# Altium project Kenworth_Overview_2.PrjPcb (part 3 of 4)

## Sheet Special_Equipment_Cabinet_Overview.SchDoc: <Document>
size Letter; Engineer: <Engineer>; Organization: UPEL; Address1: USU Power Electronics Lab; Address2: USTAR Building 620, RM 118; Address3: 1600 N 620 E; Address4: North Logan, UT 84341; DocumentNumber: 2; Revision: v1; SheetNumber: 2; SheetTotal: 16
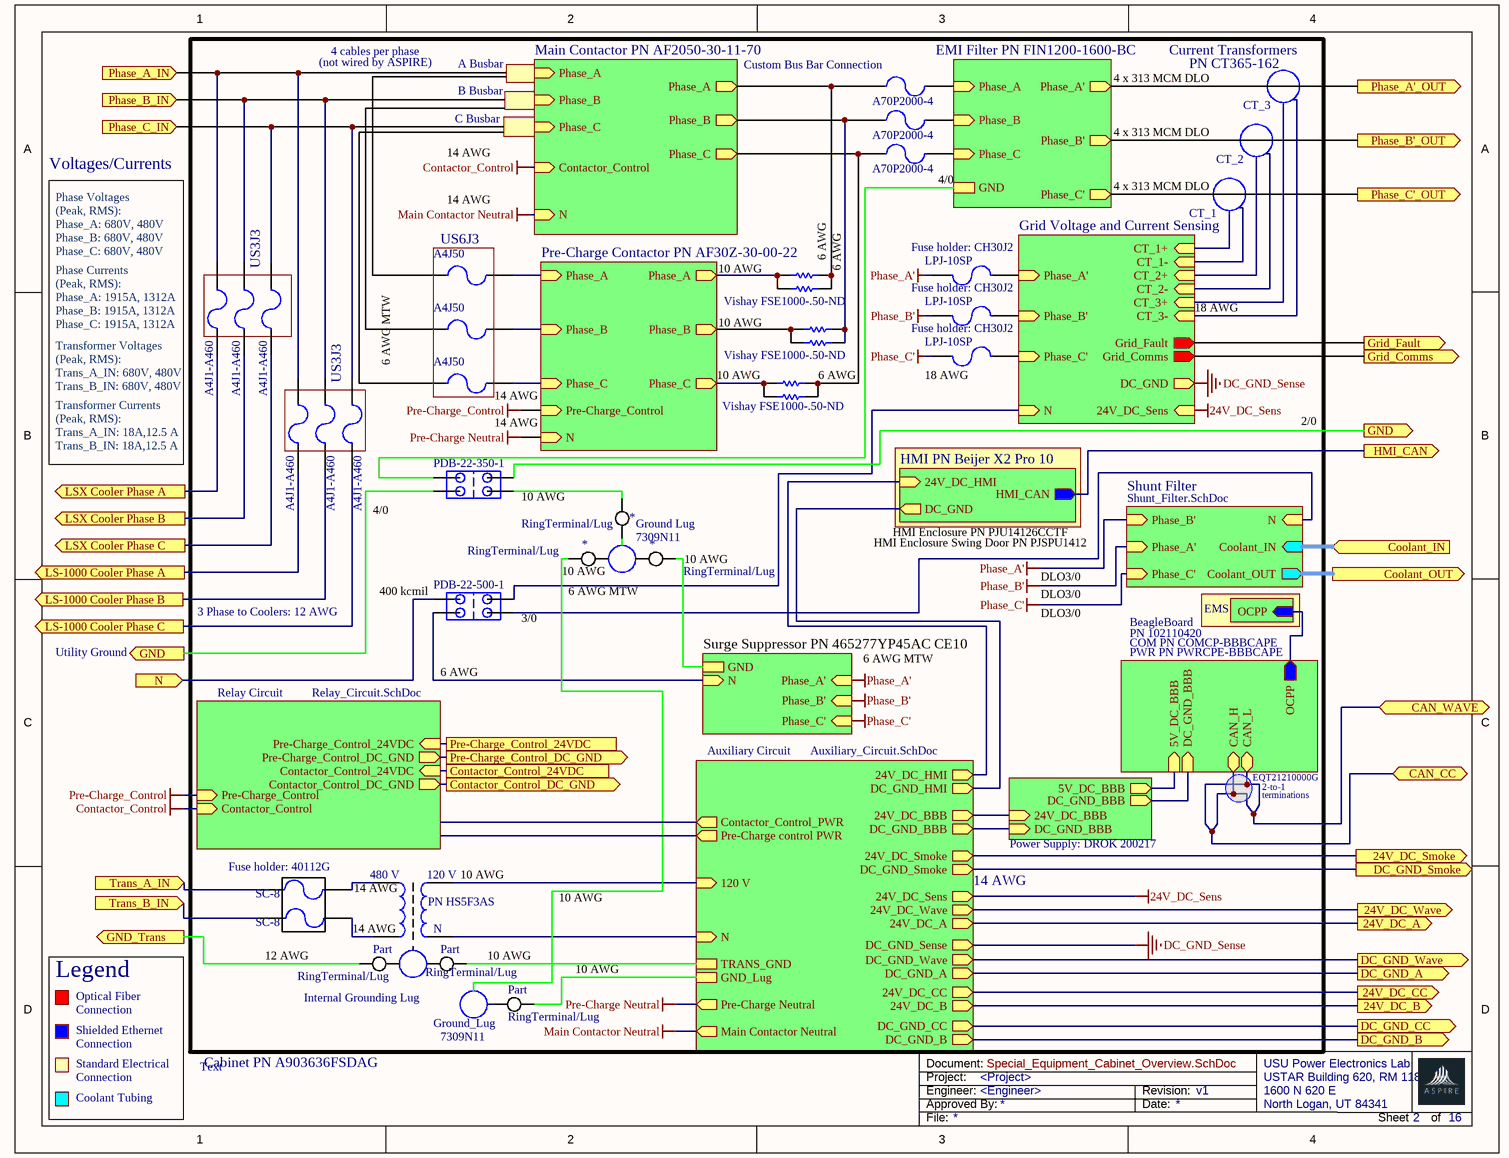
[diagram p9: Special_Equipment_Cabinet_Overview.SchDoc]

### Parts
(Parts that share a designator on the sheet are numbered #1, #2 ... from top to bottom, then left to right.)
7309N11#2  Ground_Lug_Three_Pin  (value not drawn)
7309N11#3  Ground_Lug_Three_Pin  (value not drawn)
7309N11#4  Ground_Lug
*#2  CT_3
*#3  CT_2
*#4  CT_1
*#5  RingTerminal/Lug
*#6  RingTerminal/Lug
*#7  RingTerminal/Lug
F64  A70P2000-4  [PIN-W2/E2.8]
F65  A70P2000-4  [PIN-W2/E2.8]
F66  A70P2000-4  [PIN-W2/E2.8]
F67  A4J50  [PIN-W2/E2.8]
F68  Fuse 2  [PIN-W2/E2.8]  (value not drawn)
F69  A4J50  [PIN-W2/E2.8]
F70  Fuse 2  [PIN-W2/E2.8]  (value not drawn)
F71  A4J50  [PIN-W2/E2.8]
F72  Fuse 2  [PIN-W2/E2.8]  (value not drawn)
F?#1  A4J1-A460  [PIN-W2/E2.8]
F?#2  A4J1-A460  [PIN-W2/E2.8]
F?#3  A4J1-A460  [PIN-W2/E2.8]
F?#4  A4J1-A460  [PIN-W2/E2.8]
F?#5  A4J1-A460  [PIN-W2/E2.8]
F?#6  A4J1-A460  [PIN-W2/E2.8]
J16  PDB-22-350-1
J17  PDB-22-500-1
Part#1  RingTerminal/Lug
Part#2  RingTerminal/Lug
Part#3  RingTerminal/Lug
SC-8#1  Fuse 2  [PIN-W2/E2.8]  (value not drawn)
SC-8#2  Fuse 2  [PIN-W2/E2.8]  (value not drawn)
T1  PN HS5F3AS  [TRANS]
Vishay_FSE1  Res1  [AXIAL-0.3]  (value not drawn)
Vishay_FSE2  Res1  [AXIAL-0.3]  (value not drawn)
Vishay_FSE3  Res1  [AXIAL-0.3]  (value not drawn)
Vishay_FSE1000-.50-ND#1  Res1  [AXIAL-0.3]  (value not drawn)
Vishay_FSE1000-.50-ND#2  Res1  [AXIAL-0.3]  (value not drawn)
Vishay_FSE1000-.50-ND#3  Res1  [AXIAL-0.3]  (value not drawn)

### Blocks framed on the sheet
US6J3: F67 F69 F71
US3J3: F?#1-F?#3
US3J3: F?#4-F?#6

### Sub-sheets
Auxiliary Circuit = Auxiliary_Circuit.SchDoc: 24V_DC_A (out), DC_GND_B (out), DC_GND_CC (out), 24V_DC_Wave (out), DC_GND_Wave (out), DC_GND_A (out), 24V_DC_CC (out), 24V_DC_B (out), 24V_DC_Sens (out), DC_GND_Sense (out), Pre-Charge Neutral (out), Main Contactor Neutral (out), 120 V (in), N (in), Contactor_Control_PWR (out), Pre-Charge control PWR (out), DC_GND_Smoke (out), 24V_DC_Smoke (out), TRANS_GND, GND_Lug, 24V_DC_HMI (out), DC_GND_HMI (out), 24V_DC_BBB (out), DC_GND_BBB (out)
BeagleBoard = File Name (file not in this document): OCPP (out), CAN_H (bidir), CAN_L (bidir), 5V_DC_BBB (in), DC_GND_BBB (in)
EMI Filter PN FIN1200-1600-BC = File Name (file not in this document): Phase_A (in), Phase_B (in), Phase_C (in), Phase_C' (out), Phase_B' (out), Phase_A' (out), GND
EMS = File Name (file not in this document): OCPP (in)
Grid Voltage and Current Sensing = File Name (file not in this document): Phase_A' (in), Phase_B' (in), Phase_C' (in), N (in), Grid_Comms (out), Grid_Fault (out), 24V_DC_Sens (in), CT_1+ (in), CT_3+ (in), CT_2+ (in), DC_GND (out), CT_1- (in), CT_2- (in), CT_3- (in)
HMI PN Beijer X2 Pro 10 = File Name (file not in this document): 24V_DC_HMI (in), HMI_CAN (out), DC_GND (out)
Main Contactor PN AF2050-30-11-70 = File Name (file not in this document): Phase_A (in), Phase_B (in), Phase_C (in), N (in), Contactor_Control (in), Phase_A (out), Phase_B (out), Phase_C (out)
Power Supply: DROK 200217 = File Name (file not in this document): 5V_DC_BBB (out), DC_GND_BBB (out), 24V_DC_BBB (in), DC_GND_BBB (in)
Pre-Charge Contactor PN AF30Z-30-00-22 = File Name (file not in this document): Phase_B (in), Phase_C (in), Phase_A (out), Phase_B (out), Phase_C (out), Phase_A (in), Pre-Charge_Control (in), N (in)
Relay Circuit = Relay_Circuit.SchDoc: Contactor_Control_24VDC (in), Pre-Charge_Control_DC_GND (out), Pre-Charge_Control (in), Pre-Charge_Control_24VDC (in), Contactor_Control (in), Contactor_Control_DC_GND (out)
Shunt Filter = Shunt_Filter.SchDoc: Phase_B' (in), Phase_A' (in), Phase_C' (in), N (in), Coolant_IN (in), Coolant_OUT (out)
Surge Suppressor PN 465277YP45AC CE10 = File Name (file not in this document): Phase_A' (in), Phase_B' (in), Phase_C' (in), N (in), GND

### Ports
24V_DC_A (out), 24V_DC_B (out), 24V_DC_CC (out), 24V_DC_Smoke (out), 24V_DC_Wave (out), CAN_CC (bidir), CAN_WAVE (bidir), Contactor_Control_24VDC, Contactor_Control_DC_GND (out), Coolant_IN (in), Coolant_OUT (out), DC_GND_A (out), DC_GND_B (out), DC_GND_CC (out), DC_GND_Smoke (out), DC_GND_Wave (out), GND (out), GND_Trans (out), Grid_Comms (out), Grid_Fault (out), HMI_CAN (out), LS-1000 Cooler Phase A (out), LS-1000 Cooler Phase B (out), LS-1000 Cooler Phase C (out), LSX Cooler Phase A (out), LSX Cooler Phase B (out), LSX Cooler Phase C (out), N (in), Phase_A'_OUT (out), Phase_A_IN (in), Phase_B'_OUT (out), Phase_B_IN (in), Phase_C'_OUT (out), Phase_C_IN (in), Pre-Charge_Control_24VDC, Pre-Charge_Control_DC_GND (out), Trans_A_IN (in), Trans_B_IN (in)

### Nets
24V_DC_Sens: sheet Grid Voltage and Current Sensing/24V_DC_Sens, sheet Auxiliary Circuit/24V_DC_Sens
Contactor_Control: sheet Main Contactor PN AF2050-30-11-70/Contactor_Control, sheet Relay Circuit/Contactor_Control
DC_GND_Sense: sheet Grid Voltage and Current Sensing/DC_GND, sheet Auxiliary Circuit/DC_GND_Sense
Main Contactor Neutral: sheet Main Contactor PN AF2050-30-11-70/N, sheet Auxiliary Circuit/Main Contactor Neutral
Phase_A': F68.2 ; sheet Surge Suppressor PN 465277YP45AC CE10/Phase_A', sheet Shunt Filter/Phase_B'
Phase_B': F70.2 ; sheet Surge Suppressor PN 465277YP45AC CE10/Phase_B', sheet Shunt Filter/Phase_A'
Phase_C': F72.2 ; sheet Surge Suppressor PN 465277YP45AC CE10/Phase_C', sheet Shunt Filter/Phase_C'
Pre-Charge Neutral: sheet Pre-Charge Contactor PN AF30Z-30-00-22/N, sheet Auxiliary Circuit/Pre-Charge Neutral
Pre-Charge_Control: sheet Pre-Charge Contactor PN AF30Z-30-00-22/Pre-Charge_Control, sheet Relay Circuit/Pre-Charge_Control
24V_DC_A: port 24V_DC_A, sheet Auxiliary Circuit/24V_DC_A
24V_DC_B: port 24V_DC_B, sheet Auxiliary Circuit/24V_DC_B
24V_DC_CC: port 24V_DC_CC, sheet Auxiliary Circuit/24V_DC_CC
24V_DC_HMI: sheet HMI PN Beijer X2 Pro 10/24V_DC_HMI, sheet Auxiliary Circuit/24V_DC_HMI
24V_DC_Smoke: port 24V_DC_Smoke, sheet Auxiliary Circuit/24V_DC_Smoke
24V_DC_Wave: port 24V_DC_Wave, sheet Auxiliary Circuit/24V_DC_Wave
120 V: T1.3 ; sheet Auxiliary Circuit/120 V
CAN_CC: port CAN_WAVE, port CAN_CC, sheet BeagleBoard/CAN_H, sheet BeagleBoard/CAN_L
Contactor_Control_24VDC: port Contactor_Control_24VDC, sheet Relay Circuit/Contactor_Control_24VDC
Contactor_Control_DC_GND: port Contactor_Control_DC_GND, sheet Relay Circuit/Contactor_Control_DC_GND
Coolant_IN: port Coolant_IN, sheet Shunt Filter/Coolant_IN
Coolant_OUT: port Coolant_OUT, sheet Shunt Filter/Coolant_OUT
DC_GND_A: port DC_GND_A, sheet Auxiliary Circuit/DC_GND_A
DC_GND_B: port DC_GND_B, sheet Auxiliary Circuit/DC_GND_B
DC_GND_CC: port DC_GND_CC, sheet Auxiliary Circuit/DC_GND_CC
DC_GND_HMI: sheet HMI PN Beijer X2 Pro 10/DC_GND, sheet Auxiliary Circuit/DC_GND_HMI
DC_GND_Smoke: port DC_GND_Smoke, sheet Auxiliary Circuit/DC_GND_Smoke
DC_GND_Wave: port DC_GND_Wave, sheet Auxiliary Circuit/DC_GND_Wave
GND: J16.2 J16.4 ; port GND
GND_Trans: Part#1.2_13 ; port GND_Trans
Grid_Comms: port Grid_Comms, sheet Grid Voltage and Current Sensing/Grid_Comms
Grid_Fault: port Grid_Fault, sheet Grid Voltage and Current Sensing/Grid_Fault
HMI_CAN: port HMI_CAN, sheet HMI PN Beijer X2 Pro 10/HMI_CAN
LS-1000 Cooler Phase A: F?#4.1 ; port LS-1000 Cooler Phase A
LS-1000 Cooler Phase B: F?#5.1 ; port LS-1000 Cooler Phase B
LS-1000 Cooler Phase C: F?#6.1 ; port LS-1000 Cooler Phase C
LSX Cooler Phase A: F?#1.1 ; port LSX Cooler Phase A
LSX Cooler Phase B: F?#2.1 ; port LSX Cooler Phase B
LSX Cooler Phase C: F?#3.1 ; port LSX Cooler Phase C
N: T1.4 ; sheet Auxiliary Circuit/N
N: J17.1 ; sheet Shunt Filter/N  [a separate net that carries the same name]
N: J17.4 ; port N  [a separate net that carries the same name]
Phase_A'_OUT: port Phase_A'_OUT, sheet EMI Filter PN FIN1200-1600-BC/Phase_A'
Phase_A_IN: F?#1.2 F?#4.2 ; port Phase_A_IN
Phase_B'_OUT: port Phase_B'_OUT, sheet EMI Filter PN FIN1200-1600-BC/Phase_B'
Phase_B_IN: F?#2.2 F?#5.2 ; port Phase_B_IN
Phase_C'_OUT: port Phase_C'_OUT, sheet EMI Filter PN FIN1200-1600-BC/Phase_C'
Phase_C_IN: F?#3.2 F?#6.2 ; port Phase_C_IN
Pre-Charge_Control_24VDC: port Pre-Charge_Control_24VDC, sheet Relay Circuit/Pre-Charge_Control_24VDC
Pre-Charge_Control_DC_GND: port Pre-Charge_Control_DC_GND, sheet Relay Circuit/Pre-Charge_Control_DC_GND
Trans_A_IN: SC-8#1.1 ; port Trans_A_IN
Trans_B_IN: SC-8#2.1 ; port Trans_B_IN
TRANS_GND: Part#2.2_12 ; sheet Auxiliary Circuit/TRANS_GND
Net7309N11#2_5: 7309N11#2.5 *#5.2_12
Net7309N11#2_5: 7309N11#2.5 *#7.2_13  [a separate net that carries the same name]
Net7309N11#2_5: 7309N11#2.5 *#6.2_12  [a separate net that carries the same name]
Net7309N11#3_5: 7309N11#3.5 Part#2.2_13
Net7309N11#3_5: 7309N11#3.5 Part#1.2_12  [a separate net that carries the same name]
Net7309N11#4_5: 7309N11#4.5 *#6.2_13
Net7309N11#4_5: 7309N11#4.5 Part#3.2_13  [a separate net that carries the same name]
Net*#2_4: *#2.4 ; sheet Grid Voltage and Current Sensing/CT_3+
Net*#2_4: *#2.4 ; sheet Grid Voltage and Current Sensing/CT_3-  [a separate net that carries the same name]
Net*#3_4: *#3.4 ; sheet Grid Voltage and Current Sensing/CT_2+
Net*#3_4: *#3.4 ; sheet Grid Voltage and Current Sensing/CT_2-  [a separate net that carries the same name]
Net*#4_4: *#4.4 ; sheet Grid Voltage and Current Sensing/CT_1+
Net*#4_4: *#4.4 ; sheet Grid Voltage and Current Sensing/CT_1-  [a separate net that carries the same name]
Net*#5_2_13: *#5.2_13 J16.1
Net*#7_2_12: *#7.2_12 ; sheet Surge Suppressor PN 465277YP45AC CE10/GND
NetF64_1: F64.1 Vishay_FSE1.2 Vishay_FSE1000-.50-ND#1.2 ; sheet Main Contactor PN AF2050-30-11-70/Phase_A
NetF64_2: F64.2 ; sheet EMI Filter PN FIN1200-1600-BC/Phase_A
NetF65_1: F65.1 Vishay_FSE2.2 Vishay_FSE1000-.50-ND#2.2 ; sheet Main Contactor PN AF2050-30-11-70/Phase_B
NetF65_2: F65.2 ; sheet EMI Filter PN FIN1200-1600-BC/Phase_B
NetF66_1: F66.1 Vishay_FSE3.2 Vishay_FSE1000-.50-ND#3.2 ; sheet Main Contactor PN AF2050-30-11-70/Phase_C
NetF66_2: F66.2 ; sheet EMI Filter PN FIN1200-1600-BC/Phase_C
NetF67_2: F67.2 ; sheet Pre-Charge Contactor PN AF30Z-30-00-22/Phase_A
NetF68_1: F68.1 ; sheet Grid Voltage and Current Sensing/Phase_A'
NetF69_2: F69.2 ; sheet Pre-Charge Contactor PN AF30Z-30-00-22/Phase_B
NetF70_1: F70.1 ; sheet Grid Voltage and Current Sensing/Phase_B'
NetF71_2: F71.2 ; sheet Pre-Charge Contactor PN AF30Z-30-00-22/Phase_C
NetF72_1: F72.1 ; sheet Grid Voltage and Current Sensing/Phase_C'
NetJ16_4: J16.4 ; sheet EMI Filter PN FIN1200-1600-BC/GND
NetJ17_2: J17.2 ; sheet Grid Voltage and Current Sensing/N
NetJ17_4: J17.4 ; sheet Surge Suppressor PN 465277YP45AC CE10/N
NetPart#3_2_12: Part#3.2_12 ; sheet Auxiliary Circuit/GND_Lug
NetSC-8#1_2: SC-8#1.2 T1.1
NetSC-8#2_2: SC-8#2.2 T1.2
NetVishay_FSE1_1: Vishay_FSE1.1 Vishay_FSE1000-.50-ND#1.1 ; sheet Pre-Charge Contactor PN AF30Z-30-00-22/Phase_A
NetVishay_FSE2_1: Vishay_FSE2.1 Vishay_FSE1000-.50-ND#2.1 ; sheet Pre-Charge Contactor PN AF30Z-30-00-22/Phase_B
NetVishay_FSE3_1: Vishay_FSE3.1 Vishay_FSE1000-.50-ND#3.1 ; sheet Pre-Charge Contactor PN AF30Z-30-00-22/Phase_C
(unnamed): sheet Auxiliary Circuit/24V_DC_BBB, sheet Power Supply: DROK 200217/24V_DC_BBB
(unnamed): sheet Auxiliary Circuit/DC_GND_BBB, sheet Power Supply: DROK 200217/DC_GND_BBB  [a separate net that carries the same name]
(unnamed): sheet BeagleBoard/OCPP, sheet EMS/OCPP  [a separate net that carries the same name]
(unnamed): sheet BeagleBoard/5V_DC_BBB, sheet Power Supply: DROK 200217/5V_DC_BBB  [a separate net that carries the same name]
(unnamed): sheet BeagleBoard/DC_GND_BBB, sheet Power Supply: DROK 200217/DC_GND_BBB  [a separate net that carries the same name]

Not connected (* = marked no-connect by the designer): F67 1; F69 1; F71 1

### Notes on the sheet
- (not wired by ASPIRE)
- 4 cables per phase
- B Busbar
- A Busbar
- (near F64) Custom Bus Bar Connection
- 4 x 313 MCM DLO
- (near *#2) Current Transformers
- (near *#2) PN CT365-162
- 14 AWG
- C Busbar
- (near *#3) 4 x 313 MCM DLO
- Voltages/Currents
- (near F66) 4/0
- (near *#4) 4 x 313 MCM DLO
- Phase Voltages
  (Peak, RMS):
  Phase_A: 680V, 480V
  Phase_B: 680V, 480V
  Phase_C: 680V, 480V
- 10 AWG
- (near Vishay_FSE1000-.50-ND#1) 6 AWG
- 6 AWG
- (near F68) Fuse holder: CH30J2
- (near F68) LPJ-10SP
- (near F?#1) Phase Currents
  (Peak, RMS):
  Phase_A: 1915A, 1312A
  Phase_B: 1915A, 1312A
  Phase_C: 1915A, 1312A
- 6 AWG MTW
- (near F70) Fuse holder: CH30J2
- (near F70) LPJ-10SP
- (near F72) LPJ-10SP
- 18 AWG
- (near F?#1) Transformer Voltages
  (Peak, RMS):
  Trans_A_IN: 680V, 480V
  Trans_B_IN: 680V, 480V
- (near F71) 14 AWG
- (near F72) 18 AWG
- 2/0
- Transformer Currents
  (Peak, RMS):
  Trans_A_IN: 18A,12.5 A
  Trans_B_IN: 18A,12.5 A
- (near J16) 10 AWG
- 4/0
- Ground Lug
- (near *#7) 10 AWG
- HMI Enclosure PN PJU14126CCTF
- HMI Enclosure Swing Door PN PJSPU1412
- 3 Phase to Coolers: 12 AWG
- (near J17) 400 kcmil
- (near J17) 3/0
- DLO3/0
- PN 102110420
- Utility Ground
- COM PN COMCP-BBBCAPE
- PWR PN PWRCPE-BBBCAPE
- EQT21210000G
- 2-to-1
- terminations
- (near SC-8#1) Fuse holder: 40112G
- (near T1) 14 AWG
- (near T1) 480 V
- (near T1) 120 V
- (near T1) 10 AWG
- (near SC-8#2) 12 AWG
- N
- Legend
- Optical Fiber
- Shielded Ethernet
- Connection
- Internal Grounding Lug
- Standard Electrical
- Coolant Tubing
- Text
- Cabinet PN A903636FSDAG

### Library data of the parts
*#2-*#4 = CT
F64-F72 F?#1-F?#6 SC-8#1 SC-8#2 = Fuse 2: Fuse
J17 = PDB-22-350-1
T1 = Trans: Transformer
Vishay_FSE1-Vishay_FSE3 Vishay_FSE1000-.50-ND#1-Vishay_FSE1000-.50-ND#3 = Res1: Resistor; Value: 1K

## Sheet Shunt_Filter.SchDoc: <Document>
size Letter; Engineer: <Engineer>; Organization: UPEL; Address1: USU Power Electronics Lab; Address2: USTAR Building 620, RM 118; Address3: 1600 N 620 E; Address4: North Logan, UT 84341; DocumentNumber: 3; Revision: v1; SheetNumber: 3; SheetTotal: 16
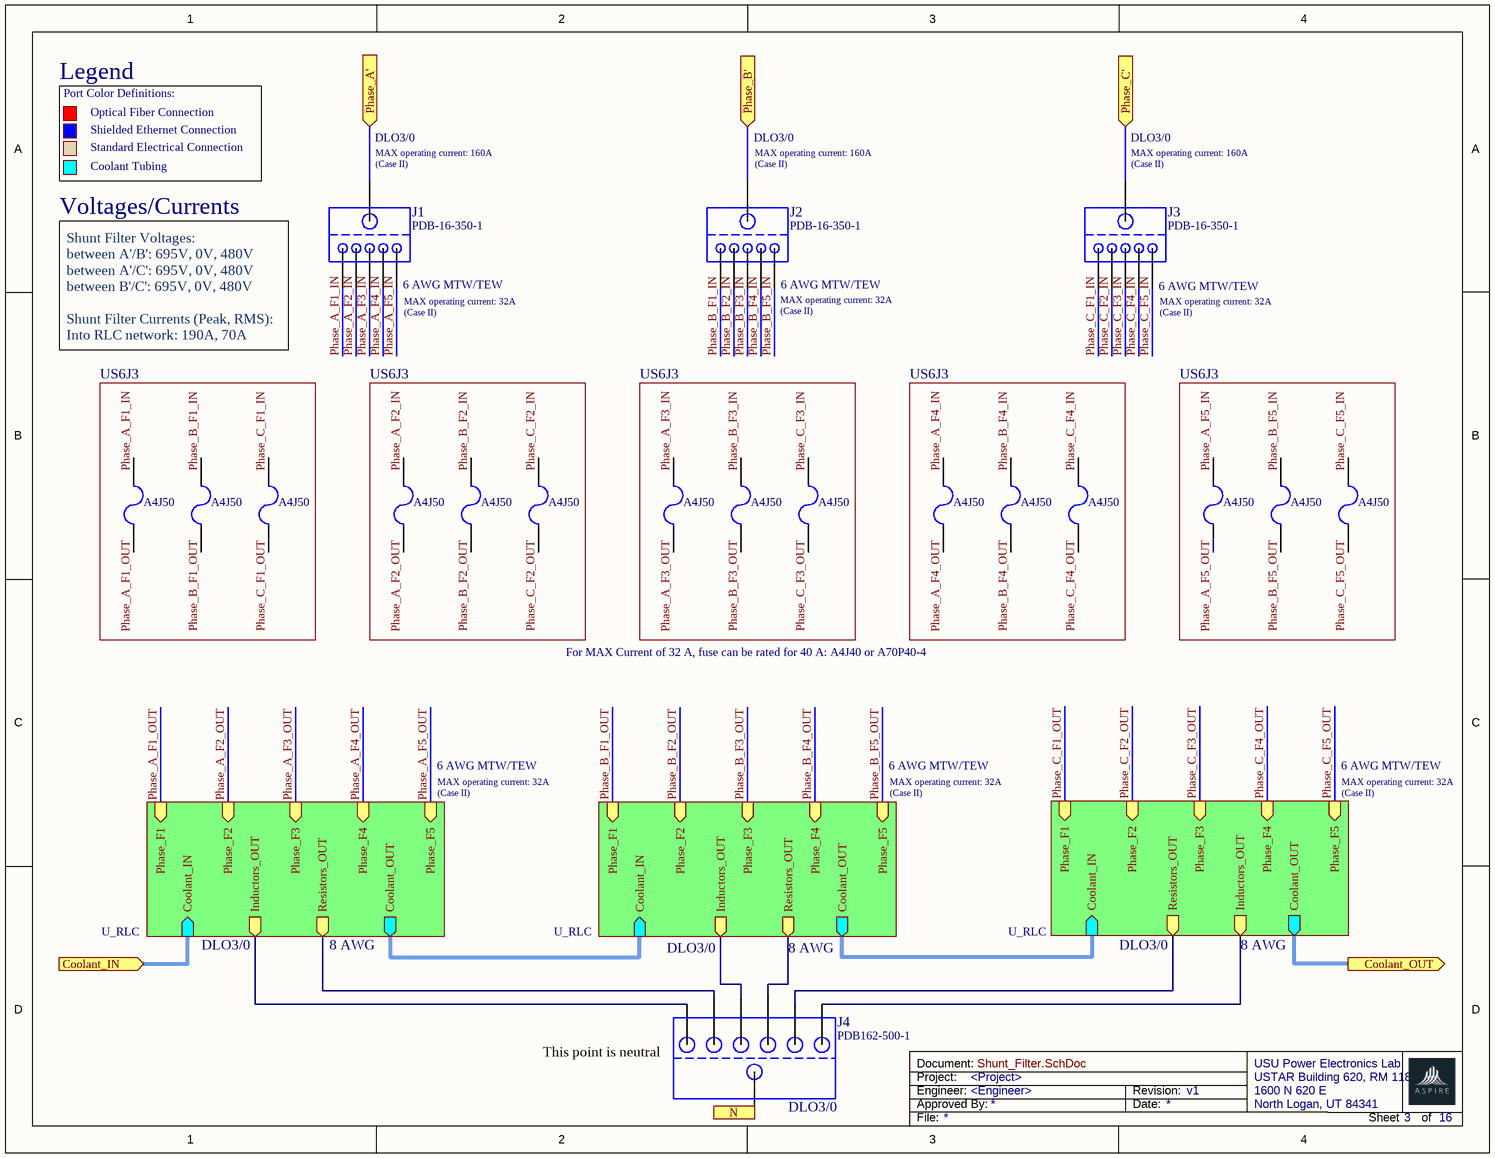
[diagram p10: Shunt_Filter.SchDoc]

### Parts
F1  A4J50  [PIN-W2/E2.8]
F2  A4J50  [PIN-W2/E2.8]
F3  A4J50  [PIN-W2/E2.8]
F4  A4J50  [PIN-W2/E2.8]
F5  A4J50  [PIN-W2/E2.8]
F7  A4J50  [PIN-W2/E2.8]
F8  A4J50  [PIN-W2/E2.8]
F9  A4J50  [PIN-W2/E2.8]
F10  A4J50  [PIN-W2/E2.8]
F11  A4J50  [PIN-W2/E2.8]
F12  A4J50  [PIN-W2/E2.8]
F13  A4J50  [PIN-W2/E2.8]
F14  A4J50  [PIN-W2/E2.8]
F15  A4J50  [PIN-W2/E2.8]
F16  A4J50  [PIN-W2/E2.8]
J1  PDB-16-350-1
J2  PDB-16-350-1
J3  PDB-16-350-1
J4  PDB162-500-1

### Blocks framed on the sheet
US6J3: F1-F3
US6J3: F4 F5 F7
US6J3: F8-F10
US6J3: F11-F13
US6J3: F14-F16

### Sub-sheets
U_RLC = RLC.SchDoc: Phase_F1 (in), Phase_F2 (in), Phase_F3 (in), Phase_F4 (in), Phase_F5 (in), Inductors_OUT (out), Resistors_OUT (out), Coolant_IN (in), Coolant_OUT (out)
U_RLC = RLC.SchDoc: Phase_F1 (in), Phase_F2 (in), Phase_F3 (in), Phase_F4 (in), Phase_F5 (in), Resistors_OUT (out), Inductors_OUT (out), Coolant_IN (in), Coolant_OUT (out)
U_RLC = RLC.SchDoc: Phase_F1 (in), Phase_F2 (in), Phase_F3 (in), Phase_F4 (in), Phase_F5 (in), Resistors_OUT (out), Inductors_OUT (out), Coolant_OUT (out), Coolant_IN (in)

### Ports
Coolant_IN (in), Coolant_OUT (out), N (in), Phase_A' (in), Phase_B' (in), Phase_C' (in)

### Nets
Phase_A': J2.0 ; port Phase_B'
Phase_B': J1.0 ; port Phase_A'
Phase_C': J3.0 ; port Phase_C'
Coolant_IN: port Coolant_IN, sheet U_RLC/Coolant_IN
Coolant_IN_U_RLC: sheet U_RLC/Coolant_OUT, sheet U_RLC/Coolant_IN
Coolant_IN_U_RLC: sheet U_RLC/Coolant_OUT, sheet U_RLC/Coolant_IN  [a separate net that carries the same name]
Coolant_OUT: port Coolant_OUT, sheet U_RLC/Coolant_OUT
Inductors_OUT: J4.0 ; sheet U_RLC/Inductors_OUT
Inductors_OUT: J4.0 ; sheet U_RLC/Inductors_OUT  [a separate net that carries the same name]
Inductors_OUT: J4.0 ; sheet U_RLC/Inductors_OUT  [a separate net that carries the same name]
N: J4.0 ; port N
Phase_A_F1_IN: J1.1
Phase_A_F2_IN: J1.2
Phase_A_F3_IN: J1.3
Phase_A_F4_IN: J1.4
Phase_A_F5_IN: J1.5
Phase_A_F5_OUT: F14.1 ; sheet U_RLC/Phase_F5
Phase_B_F1_IN: J2.1
Phase_B_F2_IN: J2.2
Phase_B_F3_IN: J2.3
Phase_B_F4_IN: J2.4
Phase_B_F5_IN: J2.5
Phase_C_F1_IN: J3.1
Phase_C_F2_IN: J3.2
Phase_C_F3_IN: J3.3
Phase_C_F4_IN: J3.4
Phase_C_F5_IN: J3.5
Resistors_OUT: J4.0 ; sheet U_RLC/Resistors_OUT
Resistors_OUT: J4.0 ; sheet U_RLC/Resistors_OUT  [a separate net that carries the same name]
Resistors_OUT: J4.0 ; sheet U_RLC/Resistors_OUT  [a separate net that carries the same name]

Not connected (* = marked no-connect by the designer): F1 1 2; F2 1 2; F3 1 2; F4 1 2; F5 1 2; F7 1 2; F8 1 2; F9 1 2; F10 1 2; F11 1 2; F12 1 2; F13 1 2; F14 2; F15 1 2; F16 1 2

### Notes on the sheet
- Legend
- Port Color Definitions:
- Optical Fiber Connection
- Shielded Ethernet Connection
- Standard Electrical Connection
- (near J1) MAX operating current: 160A
  (Case II)
- DLO3/0
- (near J2) MAX operating current: 160A
  (Case II)
- (near J3) MAX operating current: 160A
  (Case II)
- Voltages/Currents
- Coolant Tubing
- (near J1) 6 AWG MTW/TEW
- (near J2) 6 AWG MTW/TEW
- (near J3) 6 AWG MTW/TEW
- Shunt Filter Voltages:
  between A'/B': 695V, 0V, 480V
  between A'/C': 695V, 0V, 480V
  between B'/C': 695V, 0V, 480V
  Shunt Filter Currents (Peak, RMS):
  Into RLC network: 190A, 70A
- (near J1) MAX operating current: 32A
  (Case II)
- (near J2) MAX operating current: 32A
  (Case II)
- (near J3) MAX operating current: 32A
  (Case II)
- For MAX Current of 32 A, fuse can be rated for 40 A: A4J40 or A70P40-4
- 6 AWG MTW/TEW
- MAX operating current: 32A
  (Case II)
- 8 AWG
- (near J4) This point is neutral
- (near J4) DLO3/0
- Labels drawn without touching a wire or pin: Phase_A_F1_IN, Phase_A_F1_OUT, Phase_A_F2_IN, Phase_A_F2_OUT, Phase_A_F3_IN, Phase_A_F3_OUT, Phase_A_F4_IN, Phase_A_F4_OUT, Phase_A_F5_IN, Phase_B_F1_IN, Phase_B_F1_OUT, Phase_B_F2_IN, Phase_B_F2_OUT, Phase_B_F3_IN, Phase_B_F3_OUT, Phase_B_F4_IN, Phase_B_F4_OUT, Phase_B_F5_IN, Phase_B_F5_OUT, Phase_C_F1_IN, Phase_C_F1_OUT, Phase_C_F2_IN, Phase_C_F2_OUT, Phase_C_F3_IN, Phase_C_F3_OUT, Phase_C_F4_IN, Phase_C_F4_OUT, Phase_C_F5_IN, Phase_C_F5_OUT

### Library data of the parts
F1-F5 F7-F16 = Fuse 2: Fuse

## Sheet RLC.SchDoc: <Document>
size Letter; Engineer: <Engineer>; Organization: UPEL; Address1: USU Power Electronics Lab; Address2: USTAR Building 620, RM 118; Address3: 1600 N 620 E; Address4: North Logan, UT 84341; DocumentNumber: 4; Revision: v1; SheetNumber: 4; SheetTotal: 16
Used 3 times, as channels Special Equipment Cabinet/Shunt Filter/U_RLC, Special Equipment Cabinet/Shunt Filter/U_RLC, Special Equipment Cabinet/Shunt Filter/U_RLC. Parts and nets are listed once, with the designators drawn on the sheet.
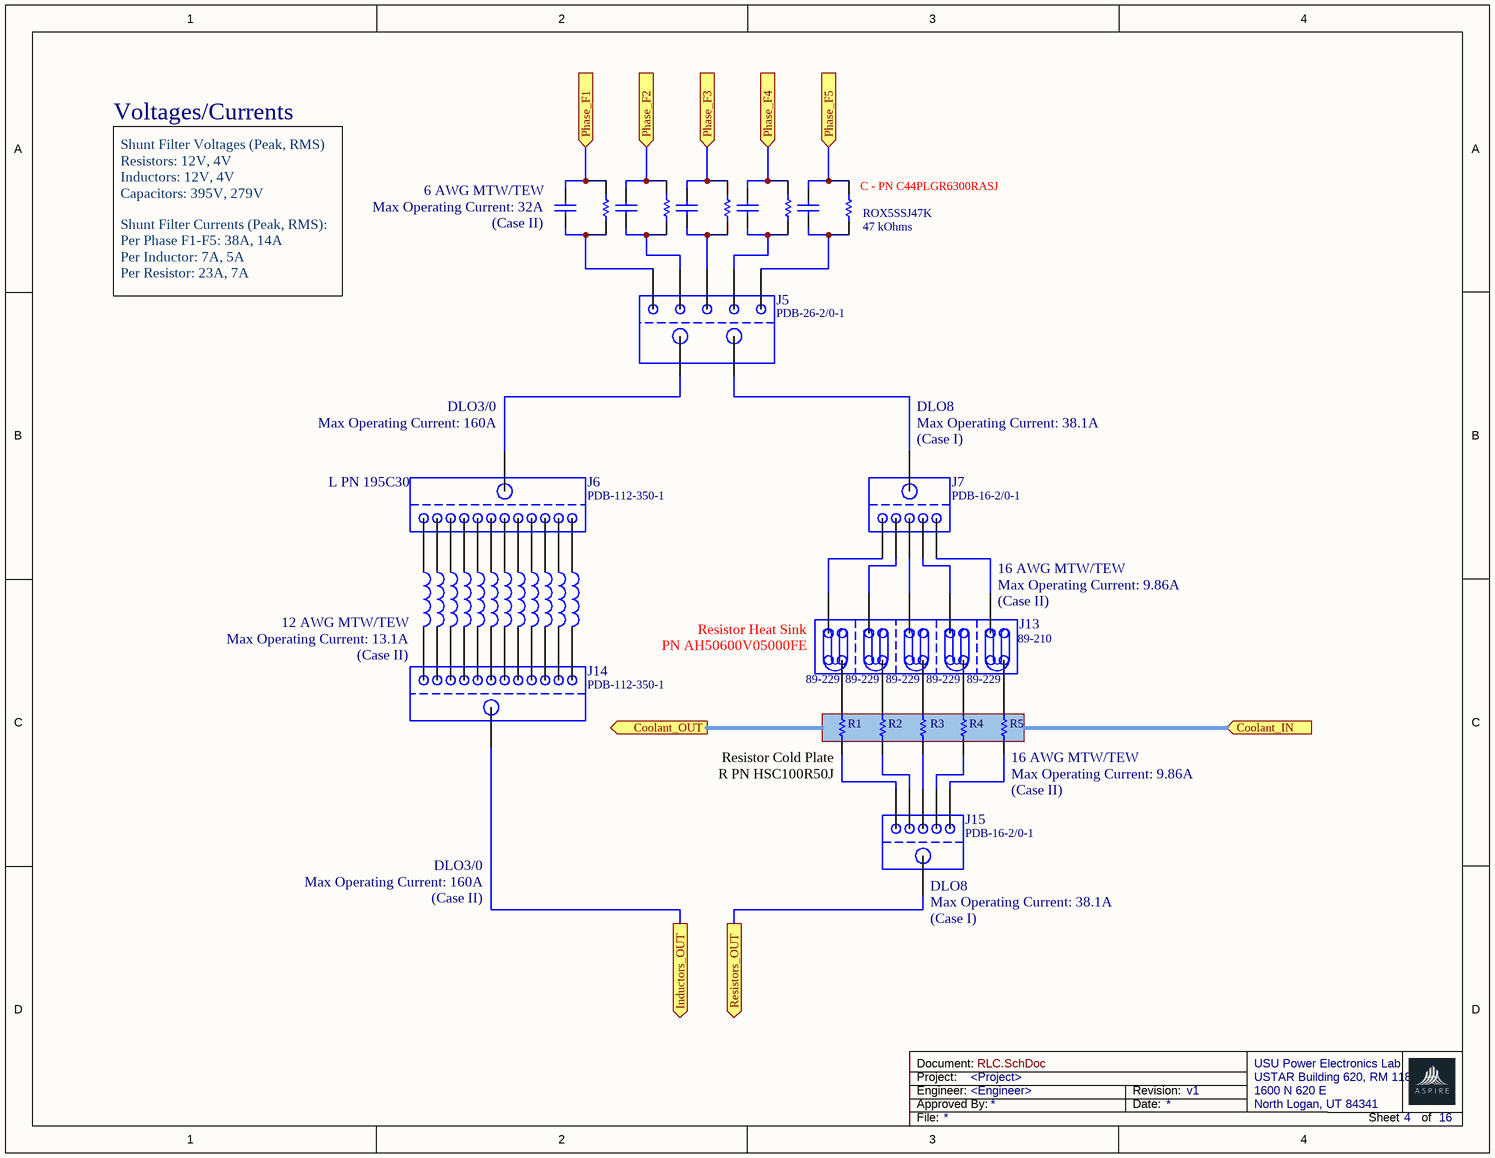
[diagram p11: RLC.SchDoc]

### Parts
(Parts that share a designator on the sheet are numbered #1, #2 ... from top to bottom, then left to right.)
C1  Cap  [RAD-0.3]  (value not drawn)
C2  Cap  [RAD-0.3]  (value not drawn)
C3  Cap  [RAD-0.3]  (value not drawn)
C4  Cap  [RAD-0.3]  (value not drawn)
C5  Cap  [RAD-0.3]  (value not drawn)
J5  PDB-26-2/0-1
J6  PDB-112-350-1
J7  PDB-16-2/0-1
J8  89-229
J9  89-229
J10  89-229
J11  89-229
J12  89-229
J13  89-210
J14  PDB-112-350-1
J15  PDB-16-2/0-1
L3  Inductor  [0402-A]  (value not drawn)
L4  Inductor  [0402-A]  (value not drawn)
L5  Inductor  [0402-A]  (value not drawn)
L6  Inductor  [0402-A]  (value not drawn)
L7  Inductor  [0402-A]  (value not drawn)
L8  Inductor  [0402-A]  (value not drawn)
L9  Inductor  [0402-A]  (value not drawn)
L10  Inductor  [0402-A]  (value not drawn)
L11  Inductor  [0402-A]  (value not drawn)
L12  Inductor  [0402-A]  (value not drawn)
L13  Inductor  [0402-A]  (value not drawn)
L14  Inductor  [0402-A]  (value not drawn)
R1  {Rsh}  [AXIAL-0.3]  (value not drawn)
R2  {Rsh}  [AXIAL-0.3]  (value not drawn)
R3  {Rsh}  [AXIAL-0.3]  (value not drawn)
R4  {Rsh}  [AXIAL-0.3]  (value not drawn)
R5  {Rsh}  [AXIAL-0.3]  (value not drawn)
ROX5SSJ47K  47 kOhms
ROX?#1  47 kOhms  (value not drawn)
ROX?#2  47 kOhms  (value not drawn)
ROX?#3  47 kOhms  (value not drawn)
ROX?#4  47 kOhms  (value not drawn)

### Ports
Coolant_IN (in), Coolant_OUT (out), Inductors_OUT (out), Phase_F1 (in), Phase_F2 (in), Phase_F3 (in), Phase_F4 (in), Phase_F5 (in), Resistors_OUT (out)

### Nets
Inductors_OUT: J14.0 ; port Inductors_OUT
Phase_F1: C1.2 ROX?#1.2 ; port Phase_F1
Phase_F2: C2.2 ROX?#2.2 ; port Phase_F2
Phase_F3: C3.2 ROX?#3.2 ; port Phase_F3
Phase_F4: C4.2 ROX?#4.2 ; port Phase_F4
Phase_F5: C5.2 ROX5SSJ47K.2 ; port Phase_F5
Resistors_OUT: J15.0 ; port Resistors_OUT
NetC1_1: C1.1 J5.5 ROX?#1.1
NetC2_1: C2.1 J5.4 ROX?#2.1
NetC3_1: C3.1 J5.3 ROX?#3.1
NetC4_1: C4.1 J5.2 ROX?#4.1
NetC5_1: C5.1 J5.1 ROX5SSJ47K.1
NetJ5_0: J5.0 J6.0
NetJ5_0: J5.0 J7.0  [a separate net that carries the same name]
NetJ6_1: J6.1 L3.1
NetJ6_1: J6.1 L5.1  [a separate net that carries the same name]
NetJ6_1: J6.1 L14.1  [a separate net that carries the same name]
NetJ6_2: J6.2 L4.1
NetJ6_2: J6.2 L6.1  [a separate net that carries the same name]
NetJ6_2: J6.2 L13.1  [a separate net that carries the same name]
NetJ6_3: J6.3 L7.1
NetJ6_3: J6.3 L10.1  [a separate net that carries the same name]
NetJ6_4: J6.4 L8.1
NetJ6_4: J6.4 L11.1  [a separate net that carries the same name]
NetJ6_5: J6.5 L9.1
NetJ6_5: J6.5 L12.1  [a separate net that carries the same name]
NetJ7_1: J7.1 J13.6
NetJ7_2: J7.2 J13.7
NetJ7_3: J7.3 J13.8
NetJ7_4: J7.4 J13.9
NetJ7_5: J7.5 J13.10
NetJ13_11: J13.11 R1.2
NetJ13_12: J13.12 R2.2
NetJ13_13: J13.13 R3.2
NetJ13_14: J13.14 R4.2
NetJ13_15: J13.15 R5.2
NetJ14_1: J14.1 L7.2
NetJ14_1: J14.1 L10.2  [a separate net that carries the same name]
NetJ14_1: J14.1 L12.2  [a separate net that carries the same name]
NetJ14_2: J14.2 L6.2
NetJ14_2: J14.2 L11.2  [a separate net that carries the same name]
NetJ14_2: J14.2 L13.2  [a separate net that carries the same name]
NetJ14_3: J14.3 L5.2
NetJ14_3: J14.3 L14.2  [a separate net that carries the same name]
NetJ14_4: J14.4 L4.2
NetJ14_4: J14.4 L9.2  [a separate net that carries the same name]
NetJ14_5: J14.5 L3.2
NetJ14_5: J14.5 L8.2  [a separate net that carries the same name]
NetJ15_1: J15.1 R5.1
NetJ15_2: J15.2 R4.1
NetJ15_3: J15.3 R3.1
NetJ15_4: J15.4 R2.1
NetJ15_5: J15.5 R1.1

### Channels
Special Equipment Cabinet/Shunt Filter/U_RLC: designators C1=C1_Special_Equipment_Cabinet_Shunt_Filter_U_RLC#1 C2=C2_Special_Equipment_Cabinet_Shunt_Filter_U_RLC#1 C3=C3_Special_Equipment_Cabinet_Shunt_Filter_U_RLC#1 C4=C4_Special_Equipment_Cabinet_Shunt_Filter_U_RLC#1 C5=C5_Special_Equipment_Cabinet_Shunt_Filter_U_RLC#1 J5=J5_Special_Equipment_Cabinet_Shunt_Filter_U_RLC#1 J6=J6_Special_Equipment_Cabinet_Shunt_Filter_U_RLC#1 J7=J7_Special_Equipment_Cabinet_Shunt_Filter_U_RLC#1 J8=J8_Special_Equipment_Cabinet_Shunt_Filter_U_RLC#1 J9=J9_Special_Equipment_Cabinet_Shunt_Filter_U_RLC#1 J10=J10_Special_Equipment_Cabinet_Shunt_Filter_U_RLC#1 J11=J11_Special_Equipment_Cabinet_Shunt_Filter_U_RLC#1 J12=J12_Special_Equipment_Cabinet_Shunt_Filter_U_RLC#1 J13=J13_Special_Equipment_Cabinet_Shunt_Filter_U_RLC#1 J14=J14_Special_Equipment_Cabinet_Shunt_Filter_U_RLC#1 J15=J15_Special_Equipment_Cabinet_Shunt_Filter_U_RLC#1 L3=L3_Special_Equipment_Cabinet_Shunt_Filter_U_RLC#1 L4=L4_Special_Equipment_Cabinet_Shunt_Filter_U_RLC#1 L5=L5_Special_Equipment_Cabinet_Shunt_Filter_U_RLC#1 L6=L6_Special_Equipment_Cabinet_Shunt_Filter_U_RLC#1 L7=L7_Special_Equipment_Cabinet_Shunt_Filter_U_RLC#1 L8=L8_Special_Equipment_Cabinet_Shunt_Filter_U_RLC#1 L9=L9_Special_Equipment_Cabinet_Shunt_Filter_U_RLC#1 L10=L10_Special_Equipment_Cabinet_Shunt_Filter_U_RLC#1 L11=L11_Special_Equipment_Cabinet_Shunt_Filter_U_RLC#1 L12=L12_Special_Equipment_Cabinet_Shunt_Filter_U_RLC#1 L13=L13_Special_Equipment_Cabinet_Shunt_Filter_U_RLC#1 L14=L14_Special_Equipment_Cabinet_Shunt_Filter_U_RLC#1 R1=R1_Special_Equipment_Cabinet_Shunt_Filter_U_RLC#1 R2=R2_Special_Equipment_Cabinet_Shunt_Filter_U_RLC#1 R3=R3_Special_Equipment_Cabinet_Shunt_Filter_U_RLC#1 R4=R4_Special_Equipment_Cabinet_Shunt_Filter_U_RLC#1 R5=R5_Special_Equipment_Cabinet_Shunt_Filter_U_RLC#1 ROX5SSJ47K=ROX5SSJ47K_Special_Equipment_Cabinet_Shunt_Filter_U_RLC#1 ROX?=ROX?_Special_Equipment_Cabinet_Shunt_Filter_U_RLC#3 ROX?=ROX?_Special_Equipment_Cabinet_Shunt_Filter_U_RLC#1 ROX?=ROX?_Special_Equipment_Cabinet_Shunt_Filter_U_RLC#2 ROX?=ROX?_Special_Equipment_Cabinet_Shunt_Filter_U_RLC#4; ports Coolant_IN=Coolant_IN Coolant_OUT=Coolant_IN_U_RLC Inductors_OUT=Inductors_OUT Phase_F1=Phase_A_F1_OUT Phase_F2=Phase_A_F2_OUT Phase_F3=Phase_A_F3_OUT Phase_F4=Phase_A_F4_OUT Phase_F5=Phase_A_F5_OUT Resistors_OUT=Resistors_OUT
Special Equipment Cabinet/Shunt Filter/U_RLC: designators C1=C1_Special_Equipment_Cabinet_Shunt_Filter_U_RLC#2 C2=C2_Special_Equipment_Cabinet_Shunt_Filter_U_RLC#2 C3=C3_Special_Equipment_Cabinet_Shunt_Filter_U_RLC#2 C4=C4_Special_Equipment_Cabinet_Shunt_Filter_U_RLC#2 C5=C5_Special_Equipment_Cabinet_Shunt_Filter_U_RLC#2 J5=J5_Special_Equipment_Cabinet_Shunt_Filter_U_RLC#2 J6=J6_Special_Equipment_Cabinet_Shunt_Filter_U_RLC#2 J7=J7_Special_Equipment_Cabinet_Shunt_Filter_U_RLC#2 J8=J8_Special_Equipment_Cabinet_Shunt_Filter_U_RLC#2 J9=J9_Special_Equipment_Cabinet_Shunt_Filter_U_RLC#2 J10=J10_Special_Equipment_Cabinet_Shunt_Filter_U_RLC#2 J11=J11_Special_Equipment_Cabinet_Shunt_Filter_U_RLC#2 J12=J12_Special_Equipment_Cabinet_Shunt_Filter_U_RLC#2 J13=J13_Special_Equipment_Cabinet_Shunt_Filter_U_RLC#2 J14=J14_Special_Equipment_Cabinet_Shunt_Filter_U_RLC#2 J15=J15_Special_Equipment_Cabinet_Shunt_Filter_U_RLC#2 L3=L3_Special_Equipment_Cabinet_Shunt_Filter_U_RLC#2 L4=L4_Special_Equipment_Cabinet_Shunt_Filter_U_RLC#2 L5=L5_Special_Equipment_Cabinet_Shunt_Filter_U_RLC#2 L6=L6_Special_Equipment_Cabinet_Shunt_Filter_U_RLC#2 L7=L7_Special_Equipment_Cabinet_Shunt_Filter_U_RLC#2 L8=L8_Special_Equipment_Cabinet_Shunt_Filter_U_RLC#2 L9=L9_Special_Equipment_Cabinet_Shunt_Filter_U_RLC#2 L10=L10_Special_Equipment_Cabinet_Shunt_Filter_U_RLC#2 L11=L11_Special_Equipment_Cabinet_Shunt_Filter_U_RLC#2 L12=L12_Special_Equipment_Cabinet_Shunt_Filter_U_RLC#2 L13=L13_Special_Equipment_Cabinet_Shunt_Filter_U_RLC#2 L14=L14_Special_Equipment_Cabinet_Shunt_Filter_U_RLC#2 R1=R1_Special_Equipment_Cabinet_Shunt_Filter_U_RLC#2 R2=R2_Special_Equipment_Cabinet_Shunt_Filter_U_RLC#2 R3=R3_Special_Equipment_Cabinet_Shunt_Filter_U_RLC#2 R4=R4_Special_Equipment_Cabinet_Shunt_Filter_U_RLC#2 R5=R5_Special_Equipment_Cabinet_Shunt_Filter_U_RLC#2 ROX5SSJ47K=ROX5SSJ47K_Special_Equipment_Cabinet_Shunt_Filter_U_RLC#2 ROX?=ROX?_Special_Equipment_Cabinet_Shunt_Filter_U_RLC#7 ROX?=ROX?_Special_Equipment_Cabinet_Shunt_Filter_U_RLC#5 ROX?=ROX?_Special_Equipment_Cabinet_Shunt_Filter_U_RLC#6 ROX?=ROX?_Special_Equipment_Cabinet_Shunt_Filter_U_RLC#8; ports Coolant_IN=Coolant_IN_U_RLC Coolant_OUT=Coolant_IN_U_RLC Inductors_OUT=Inductors_OUT Phase_F1=Phase_B_F1_OUT Phase_F2=Phase_B_F2_OUT Phase_F3=Phase_B_F3_OUT Phase_F4=Phase_B_F4_OUT Phase_F5=Phase_B_F5_OUT Resistors_OUT=Resistors_OUT
Special Equipment Cabinet/Shunt Filter/U_RLC: designators C1=C1_Special_Equipment_Cabinet_Shunt_Filter_U_RLC#3 C2=C2_Special_Equipment_Cabinet_Shunt_Filter_U_RLC#3 C3=C3_Special_Equipment_Cabinet_Shunt_Filter_U_RLC#3 C4=C4_Special_Equipment_Cabinet_Shunt_Filter_U_RLC#3 C5=C5_Special_Equipment_Cabinet_Shunt_Filter_U_RLC#3 J5=J5_Special_Equipment_Cabinet_Shunt_Filter_U_RLC#3 J6=J6_Special_Equipment_Cabinet_Shunt_Filter_U_RLC#3 J7=J7_Special_Equipment_Cabinet_Shunt_Filter_U_RLC#3 J8=J8_Special_Equipment_Cabinet_Shunt_Filter_U_RLC#3 J9=J9_Special_Equipment_Cabinet_Shunt_Filter_U_RLC#3 J10=J10_Special_Equipment_Cabinet_Shunt_Filter_U_RLC#3 J11=J11_Special_Equipment_Cabinet_Shunt_Filter_U_RLC#3 J12=J12_Special_Equipment_Cabinet_Shunt_Filter_U_RLC#3 J13=J13_Special_Equipment_Cabinet_Shunt_Filter_U_RLC#3 J14=J14_Special_Equipment_Cabinet_Shunt_Filter_U_RLC#3 J15=J15_Special_Equipment_Cabinet_Shunt_Filter_U_RLC#3 L3=L3_Special_Equipment_Cabinet_Shunt_Filter_U_RLC#3 L4=L4_Special_Equipment_Cabinet_Shunt_Filter_U_RLC#3 L5=L5_Special_Equipment_Cabinet_Shunt_Filter_U_RLC#3 L6=L6_Special_Equipment_Cabinet_Shunt_Filter_U_RLC#3 L7=L7_Special_Equipment_Cabinet_Shunt_Filter_U_RLC#3 L8=L8_Special_Equipment_Cabinet_Shunt_Filter_U_RLC#3 L9=L9_Special_Equipment_Cabinet_Shunt_Filter_U_RLC#3 L10=L10_Special_Equipment_Cabinet_Shunt_Filter_U_RLC#3 L11=L11_Special_Equipment_Cabinet_Shunt_Filter_U_RLC#3 L12=L12_Special_Equipment_Cabinet_Shunt_Filter_U_RLC#3 L13=L13_Special_Equipment_Cabinet_Shunt_Filter_U_RLC#3 L14=L14_Special_Equipment_Cabinet_Shunt_Filter_U_RLC#3 R1=R1_Special_Equipment_Cabinet_Shunt_Filter_U_RLC#3 R2=R2_Special_Equipment_Cabinet_Shunt_Filter_U_RLC#3 R3=R3_Special_Equipment_Cabinet_Shunt_Filter_U_RLC#3 R4=R4_Special_Equipment_Cabinet_Shunt_Filter_U_RLC#3 R5=R5_Special_Equipment_Cabinet_Shunt_Filter_U_RLC#3 ROX5SSJ47K=ROX5SSJ47K_Special_Equipment_Cabinet_Shunt_Filter_U_RLC#3 ROX?=ROX?_Special_Equipment_Cabinet_Shunt_Filter_U_RLC#11 ROX?=ROX?_Special_Equipment_Cabinet_Shunt_Filter_U_RLC#9 ROX?=ROX?_Special_Equipment_Cabinet_Shunt_Filter_U_RLC#10 ROX?=ROX?_Special_Equipment_Cabinet_Shunt_Filter_U_RLC#12; ports Coolant_IN=Coolant_IN_U_RLC Coolant_OUT=Coolant_OUT Inductors_OUT=Inductors_OUT Phase_F1=Phase_C_F1_OUT Phase_F2=Phase_C_F2_OUT Phase_F3=Phase_C_F3_OUT Phase_F4=Phase_C_F4_OUT Phase_F5=Phase_C_F5_OUT Resistors_OUT=Resistors_OUT

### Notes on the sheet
- Voltages/Currents
- Shunt Filter Voltages (Peak, RMS)
  Resistors: 12V, 4V
  Inductors: 12V, 4V
  Capacitors: 395V, 279V
- (near C1) 6 AWG MTW/TEW
  Max Operating Current: 32A
  (Case II)
- (near ROX5SSJ47K) C - PN C44PLGR6300RASJ
- Shunt Filter Currents (Peak, RMS):
  Per Phase F1-F5: 38A, 14A
  Per Inductor: 7A, 5A
  Per Resistor: 23A, 7A
- DLO3/0
  Max Operating Current: 160A
- (near J6) L PN 195C30
- (near J7) DLO8
  Max Operating Current: 38.1A
  (Case I)
- 16 AWG MTW/TEW
  Max Operating Current: 9.86A
  (Case II)
- 12 AWG MTW/TEW
  Max Operating Current: 13.1A
  (Case II)
- (near J13) Resistor Heat Sink
  PN AH50600V05000FE
- (near R1) Resistor Cold Plate
  R PN HSC100R50J
- (near R5) 16 AWG MTW/TEW
  Max Operating Current: 9.86A
  (Case II)
- DLO3/0
  Max Operating Current: 160A
  (Case II)
- (near J15) DLO8
  Max Operating Current: 38.1A
  (Case I)

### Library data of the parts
C1-C5 = Cap: Capacitor; Value: {Csh}
L3-L14 = Inductor: Code_IEC: 1005; Value: {Lsh}
R1-R5 = Res1: Resistor; Value: 1K
ROX5SSJ47K ROX?#1-ROX?#4 = Resistor: TC1: 0; SimulationGenericComponent: True; Value: 1K

## Sheet Auxiliary_Circuit.SchDoc: <Document>
size Letter; Engineer: <Engineer>; Organization: UPEL; Address1: USU Power Electronics Lab; Address2: USTAR Building 620, RM 118; Address3: 1600 N 620 E; Address4: North Logan, UT 84341; DocumentNumber: 2; Revision: v1; SheetNumber: 2; SheetTotal: 16
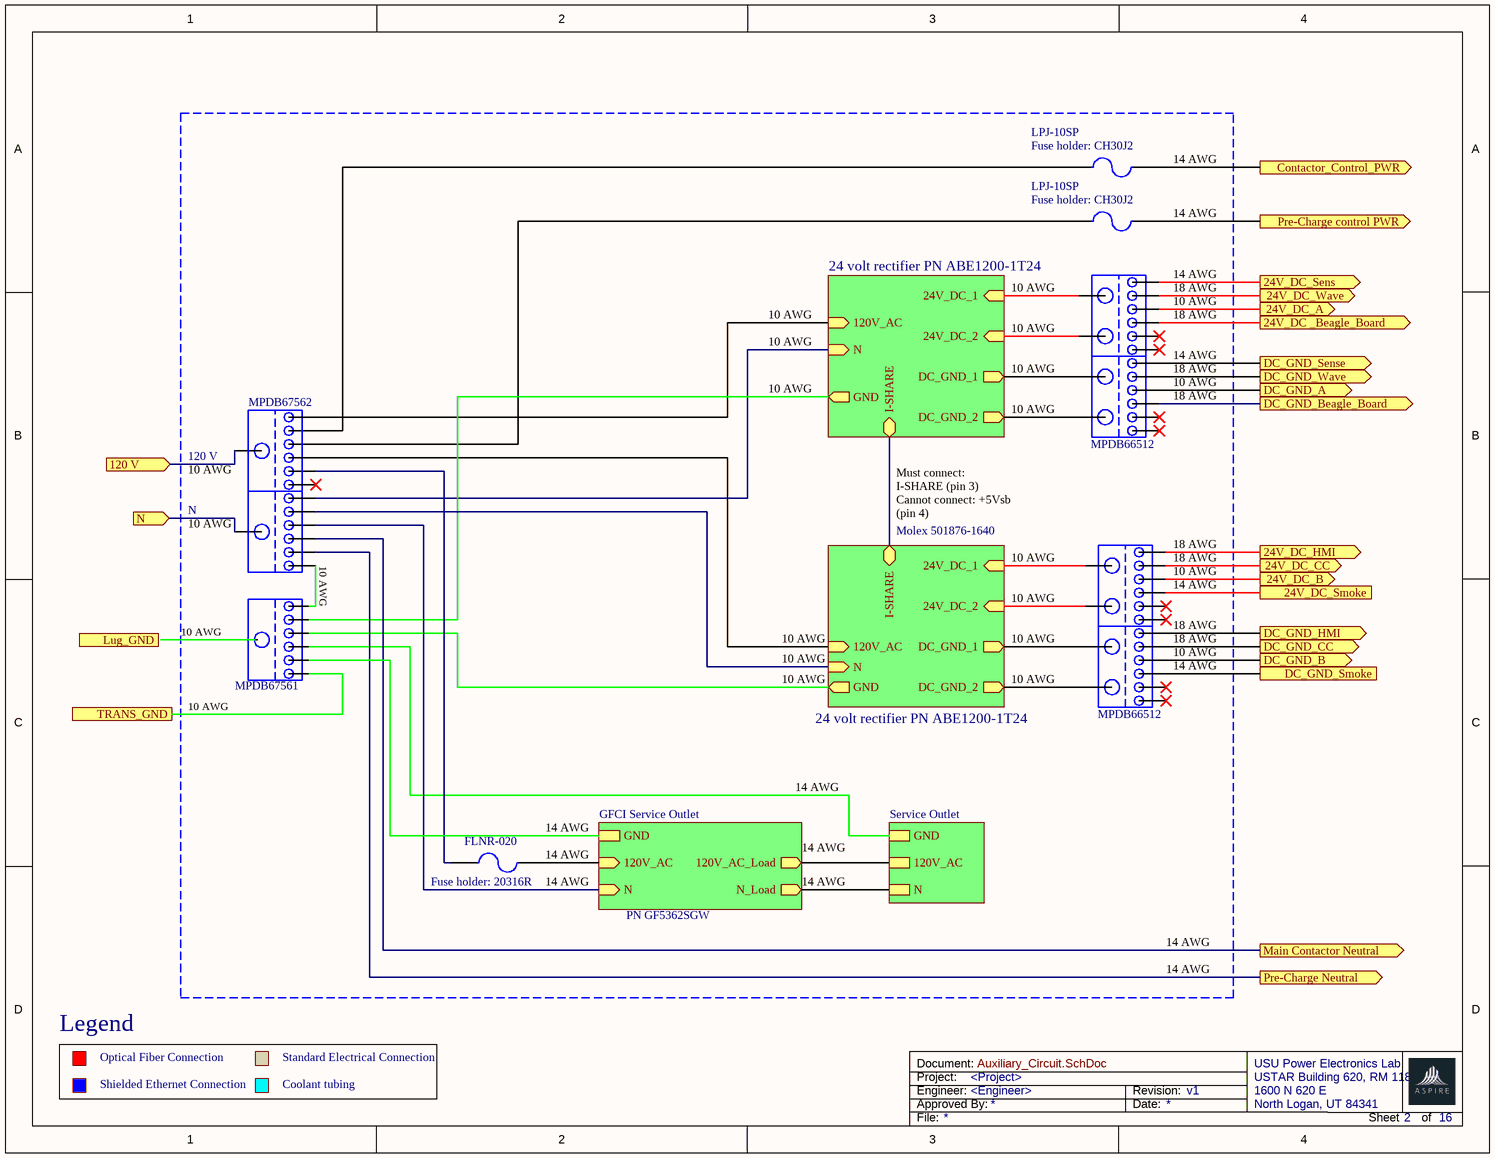
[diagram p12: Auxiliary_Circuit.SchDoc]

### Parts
(Parts that share a designator on the sheet are numbered #1, #2 ... from top to bottom, then left to right.)
*#8  MPDB67561
F73  LPJ-10SP  [PIN-W2/E2.8]
F74  LPJ-10SP  [PIN-W2/E2.8]
FLNR-020  Fuse 2  [PIN-W2/E2.8]  (value not drawn)
J18  MPDB66512
J19  MPDB67562
J20  MPDB66512

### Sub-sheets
24 volt rectifier PN ABE1200-1T24 = File Name (file not in this document): 120V_AC (in), N (in), 24V_DC_1 (in), DC_GND_1 (out), 24V_DC_2 (in), DC_GND_2 (out), GND (out), I-SHARE (bidir)
24 volt rectifier PN ABE1200-1T24 = File Name (file not in this document): 120V_AC (in), N (in), 24V_DC_1 (in), DC_GND_1 (out), 24V_DC_2 (in), DC_GND_2 (out), GND (out), I-SHARE (bidir)
GFCI Service Outlet = File Name (file not in this document): GND, 120V_AC (in), N (in), 120V_AC_Load (out), N_Load (out)
Service Outlet = File Name (file not in this document): GND, 120V_AC, N

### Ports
24V_DC _Beagle_Board (out), 24V_DC_A (out), 24V_DC_B (out), 24V_DC_CC (out), 24V_DC_HMI (out), 24V_DC_Sens (out), 24V_DC_Smoke, 24V_DC_Wave (out), 120 V (in), Contactor_Control_PWR (out), DC_GND_A (out), DC_GND_B (out), DC_GND_Beagle_Board (out), DC_GND_CC (out), DC_GND_HMI (out), DC_GND_Sense (out), DC_GND_Smoke, DC_GND_Wave (out), Lug_GND, Main Contactor Neutral (out), N (in), Pre-Charge control PWR (out), Pre-Charge Neutral (out), TRANS_GND

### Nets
24V_DC_Sens: J18.2 ; port 24V_DC_Sens
DC_GND_Sense: J18.2 ; port DC_GND_Sense
Main Contactor Neutral: J19.1 ; port Main Contactor Neutral
Pre-Charge Neutral: J19.1 ; port Pre-Charge Neutral
24V_DC _Beagle_Board: J18.1 ; port 24V_DC _Beagle_Board
24V_DC_A: J18.2 ; port 24V_DC_A
24V_DC_B: J20.2 ; port 24V_DC_B
24V_DC_CC: J20.1 ; port 24V_DC_CC
24V_DC_HMI: J20.2 ; port 24V_DC_HMI
24V_DC_Smoke: J20.1 ; port 24V_DC_Smoke
24V_DC_Wave: J18.1 ; port 24V_DC_Wave
120 V: J19.0 ; port 120 V
Contactor_Control_PWR: F73.2 ; port Contactor_Control_PWR
DC_GND_A: J18.2 ; port DC_GND_A
DC_GND_B: J20.2 ; port DC_GND_B
DC_GND_Beagle_Board: J18.1 ; port DC_GND_Beagle_Board
DC_GND_CC: J20.1 ; port DC_GND_CC
DC_GND_HMI: J20.2 ; port DC_GND_HMI
DC_GND_Smoke: J20.1 ; port DC_GND_Smoke
DC_GND_Wave: J18.1 ; port DC_GND_Wave
N: J19.0 ; port N
Pre-Charge control PWR: F74.2 ; port Pre-Charge control PWR
NetF73_1: F73.1 J19.5
NetF74_1: F74.1 J19.4
NetFLNR-020_1: FLNR-020.1 J19.3
NetFLNR-020_2: FLNR-020.2 ; sheet GFCI Service Outlet/120V_AC
NetJ18_0: J18.0 ; sheet 24 volt rectifier PN ABE1200-1T24/DC_GND_2
NetJ18_0: J18.0 ; sheet 24 volt rectifier PN ABE1200-1T24/DC_GND_1  [a separate net that carries the same name]
NetJ18_0: J18.0 ; sheet 24 volt rectifier PN ABE1200-1T24/24V_DC_2  [a separate net that carries the same name]
NetJ18_0: J18.0 ; sheet 24 volt rectifier PN ABE1200-1T24/24V_DC_1  [a separate net that carries the same name]
NetJ19_1: J19.1 ; sheet 24 volt rectifier PN ABE1200-1T24/N
NetJ19_1: J19.1 ; sheet 24 volt rectifier PN ABE1200-1T24/120V_AC  [a separate net that carries the same name]
NetJ19_1: J19.1 ; sheet 24 volt rectifier PN ABE1200-1T24/N  [a separate net that carries the same name]
NetJ19_2: J19.2 ; sheet GFCI Service Outlet/N
NetJ19_5: J19.5 ; sheet 24 volt rectifier PN ABE1200-1T24/120V_AC
NetJ20_0: J20.0 ; sheet 24 volt rectifier PN ABE1200-1T24/DC_GND_2
NetJ20_0: J20.0 ; sheet 24 volt rectifier PN ABE1200-1T24/DC_GND_1  [a separate net that carries the same name]
NetJ20_0: J20.0 ; sheet 24 volt rectifier PN ABE1200-1T24/24V_DC_2  [a separate net that carries the same name]
NetJ20_0: J20.0 ; sheet 24 volt rectifier PN ABE1200-1T24/24V_DC_1  [a separate net that carries the same name]
(unnamed): sheet 24 volt rectifier PN ABE1200-1T24/I-SHARE, sheet 24 volt rectifier PN ABE1200-1T24/I-SHARE
(unnamed): sheet GFCI Service Outlet/120V_AC_Load, sheet Service Outlet/120V_AC  [a separate net that carries the same name]
(unnamed): sheet GFCI Service Outlet/N_Load, sheet Service Outlet/N  [a separate net that carries the same name]

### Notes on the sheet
- (near F73) Fuse holder: CH30J2
- (near F73) 14 AWG
- (near F74) Fuse holder: CH30J2
- 14 AWG
- 10 AWG
- (near J18) 18 AWG
- (near J18) 10 AWG
- (near J18) 14 AWG
- (near J19) 10 AWG
- (near J19) 120 V
- N
- Molex 501876-1640
- Must connect: I-SHARE (pin 3)
  Cannot connect: +5Vsb (pin 4)
- (near J20) 18 AWG
- (near J20) 10 AWG
- (near J20) 14 AWG
- (near FLNR-020) 14 AWG
- (near FLNR-020) Fuse holder: 20316R
- PN GF5362SGW
- Legend
- Optical Fiber Connection
- Shielded Ethernet Connection
- Standard Electrical Connection
- Coolant tubing

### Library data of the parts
F73 F74 FLNR-020 = Fuse 2: Fuse
J19 = 2_to_12

## Sheet Relay_Circuit.SchDoc: <Document>
size Letter; Engineer: <Engineer>; Organization: UPEL; Address1: USU Power Electronics Lab; Address2: USTAR Building 620, RM 118; Address3: 1600 N 620 E; Address4: North Logan, UT 84341; DocumentNumber: 2; Revision: v1; SheetNumber: 2; SheetTotal: 16
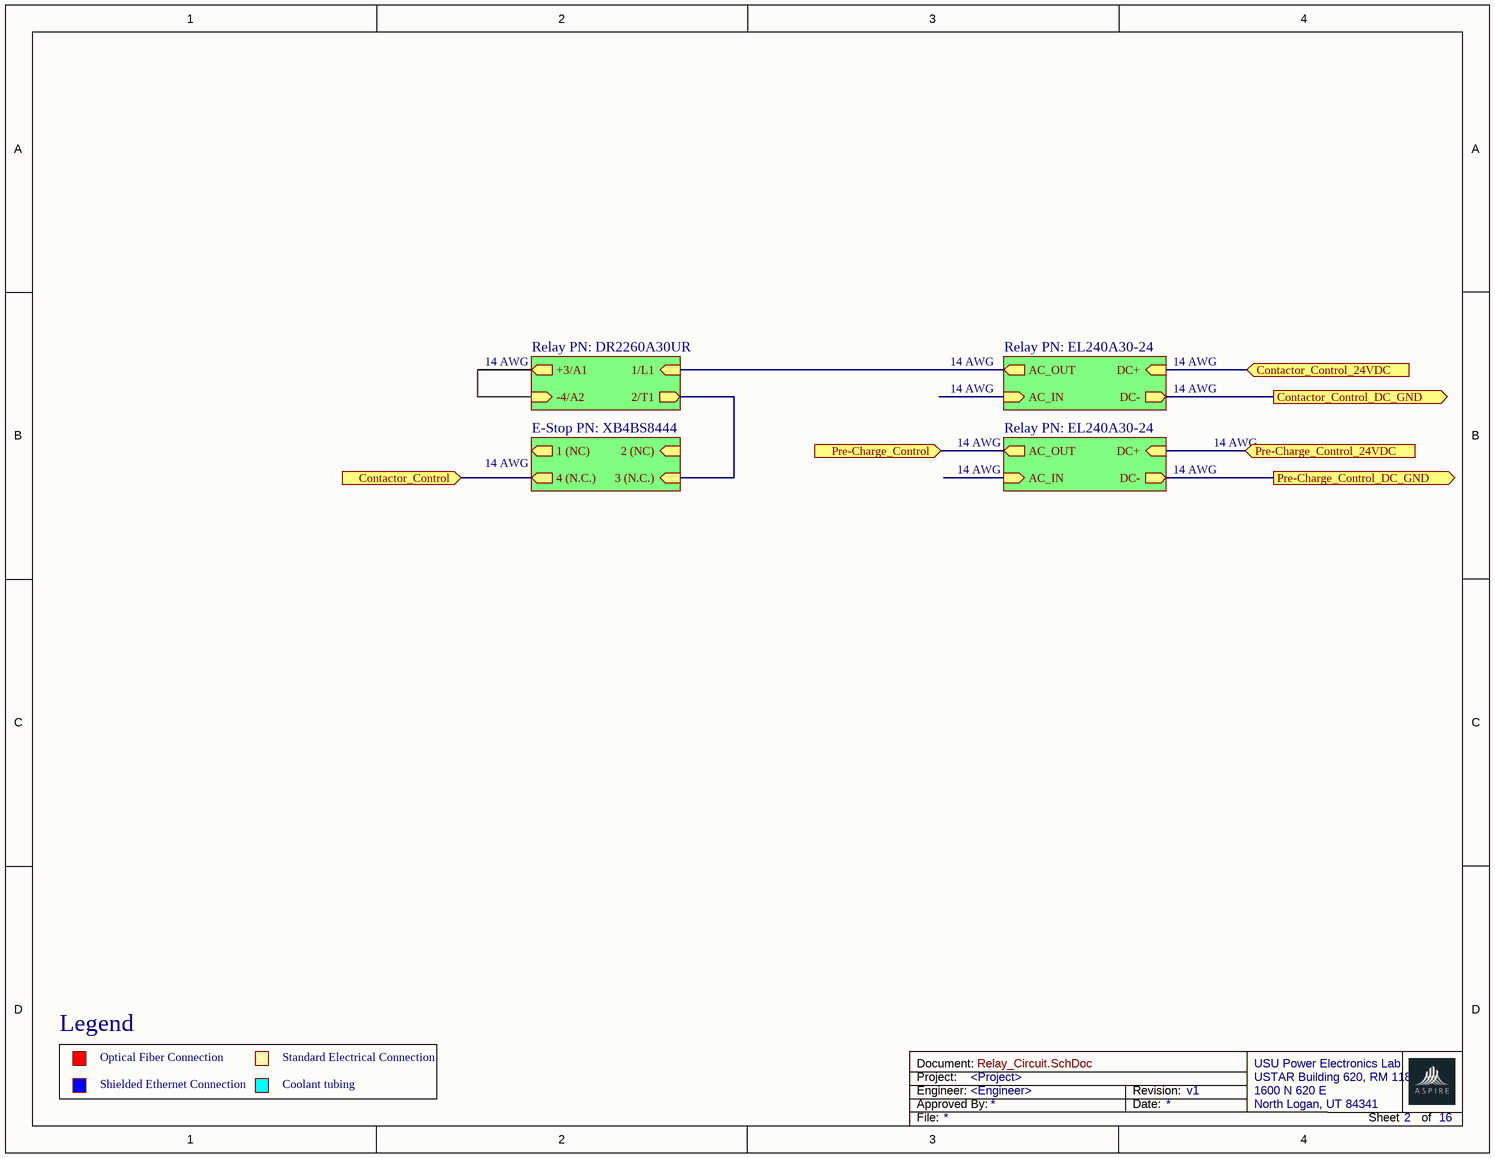
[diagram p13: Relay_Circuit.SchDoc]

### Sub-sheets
E-Stop PN: XB4BS8444 = File Name (file not in this document): 4 (N.C.) (out), 3 (N.C.) (in), 1 (NC) (out), 2 (NC) (in)
Relay PN: DR2260A30UR = File Name (file not in this document): -4/A2 (in), +3/A1 (out), 1/L1 (in), 2/T1 (out)
Relay PN: EL240A30-24 = File Name (file not in this document): AC_IN (in), AC_OUT (out), DC+ (in), DC- (out)
Relay PN: EL240A30-24 = File Name (file not in this document): AC_IN (in), AC_OUT (out), DC+ (in), DC- (out)

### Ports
Contactor_Control (in), Contactor_Control_24VDC (in), Contactor_Control_DC_GND (out), Pre-Charge_Control (in), Pre-Charge_Control_24VDC (in), Pre-Charge_Control_DC_GND (out)

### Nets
Contactor_Control: port Contactor_Control, sheet E-Stop PN: XB4BS8444/4 (N.C.)
Pre-Charge_Control: port Pre-Charge_Control, sheet Relay PN: EL240A30-24/AC_OUT
Contactor_Control_24VDC: port Contactor_Control_24VDC, sheet Relay PN: EL240A30-24/DC+
Contactor_Control_DC_GND: port Contactor_Control_DC_GND, sheet Relay PN: EL240A30-24/DC-
Pre-Charge_Control_24VDC: port Pre-Charge_Control_24VDC, sheet Relay PN: EL240A30-24/DC+
Pre-Charge_Control_DC_GND: port Pre-Charge_Control_DC_GND, sheet Relay PN: EL240A30-24/DC-
(unnamed): sheet Relay PN: EL240A30-24/AC_OUT, sheet Relay PN: DR2260A30UR/1/L1
(unnamed): sheet E-Stop PN: XB4BS8444/3 (N.C.), sheet Relay PN: DR2260A30UR/2/T1  [a separate net that carries the same name]
(unnamed): sheet Relay PN: DR2260A30UR/-4/A2, sheet Relay PN: DR2260A30UR/+3/A1  [a separate net that carries the same name]

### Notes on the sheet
- 14 AWG
- Legend
- Optical Fiber Connection
- Shielded Ethernet Connection
- Standard Electrical Connection
- Coolant tubing

## Sheet Vehicle_Charger_Hierarchal.SchDoc: <Document>
size Letter; Engineer: <Engineer>; Organization: UPEL; Address1: USU Power Electronics Lab; Address2: USTAR Building 620, RM 118; Address3: 1600 N 620 E; Address4: North Logan, UT 84341; DocumentNumber: 12; Revision: v1; SheetNumber: 12; SheetTotal: 16
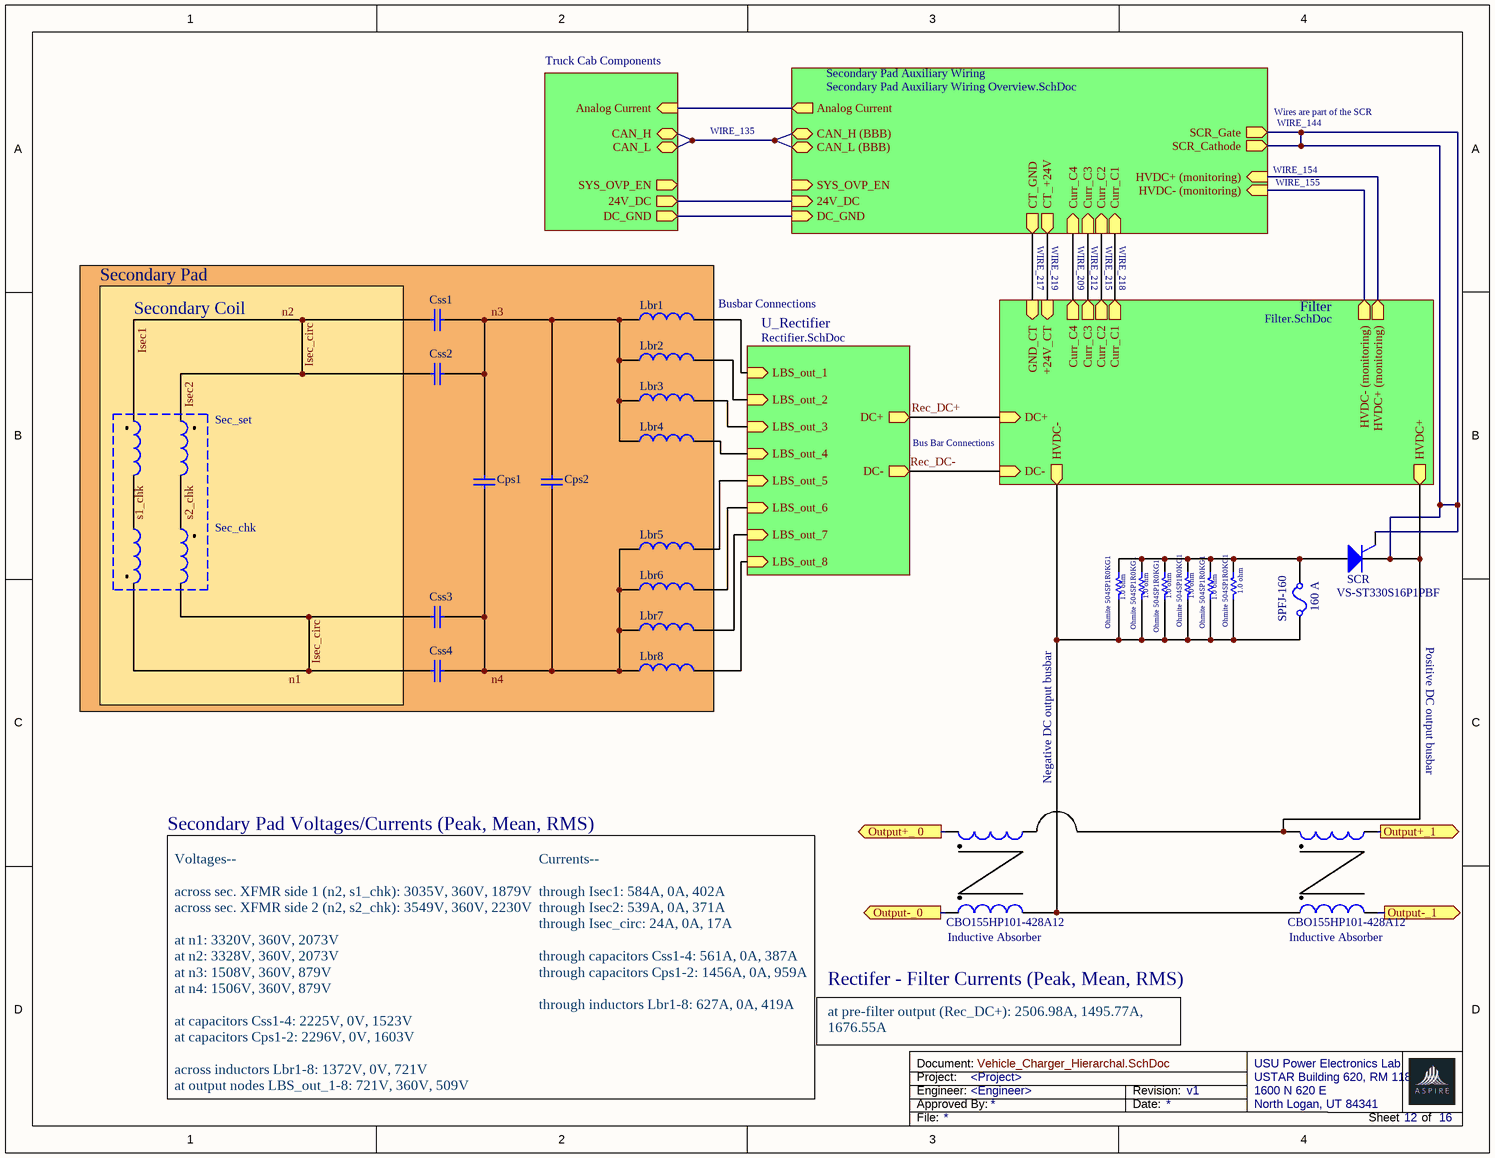
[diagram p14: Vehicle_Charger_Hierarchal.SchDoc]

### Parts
(Parts that share a designator on the sheet are numbered #1, #2 ... from top to bottom, then left to right.)
*?#1  CBO155HP101-428A12  (value not drawn)
*?#2  CBO155HP101-428A12  (value not drawn)
*?#3  CBO155HP101-428A12
*?#4  CBO155HP101-428A12
Cps1  Capacitor  (value not drawn)
Cps2  Capacitor  (value not drawn)
Css1  Capacitor  (value not drawn)
Css2  Capacitor  (value not drawn)
Css3  Capacitor  (value not drawn)
Css4  Capacitor  (value not drawn)
L?#7  Inductor  (value not drawn)
L?#8  Inductor  (value not drawn)
L?#9  Inductor  (value not drawn)
L?#10  Inductor  (value not drawn)
Lbr1  Inductor  (value not drawn)
Lbr2  Inductor  (value not drawn)
Lbr3  Inductor  (value not drawn)
Lbr4  Inductor  (value not drawn)
Lbr5  Inductor  (value not drawn)
Lbr6  Inductor  (value not drawn)
Lbr7  Inductor  (value not drawn)
Lbr8  Inductor  (value not drawn)
Ohmite_504SP1R0KG1#1  value 1.0 ohm  (hidden comment: Resistor)
Ohmite_504SP1R0KG1#2  value 1.0 ohm  (hidden comment: Resistor)
Ohmite_504SP1R0KG1#3  value 1.0 ohm  (hidden comment: Resistor)
Ohmite_504SP1R0KG1#4  value 1.0 ohm  (hidden comment: Resistor)
Ohmite_504SP1R0KG1#5  value 1.0 ohm  (hidden comment: Resistor)
Ohmite_504SP1R0KG1#6  value 1.0 ohm  (hidden comment: Resistor)
SCR  SCR Thyristror  (value not drawn)
SPFJ-160  CURRENT: 160 A  (hidden comment: Fuse)

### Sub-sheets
Filter = Filter.SchDoc: HVDC+ (out), HVDC- (out), DC- (in), DC+ (in), Curr_C1 (out), Curr_C2 (out), Curr_C3 (out), Curr_C4 (out), +24V_CT (in), GND_CT (in), HVDC- (monitoring) (out), HVDC+ (monitoring) (out)
Secondary Pad Auxiliary Wiring = Secondary Pad Auxiliary Wiring Overview.SchDoc (file not in this document): Curr_C1 (in), Curr_C2 (in), Curr_C3 (in), Curr_C4 (in), CAN_L (BBB) (bidir), CAN_H (BBB) (bidir), HVDC- (monitoring) (in), HVDC+ (monitoring) (in), CT_+24V (out), CT_GND (out), SCR_Cathode (out), SCR_Gate (out), SYS_OVP_EN (in), Analog Current (out), 24V_DC (in), DC_GND (in)
Truck Cab Components = File Name (file not in this document): Analog Current (in), 24V_DC (out), DC_GND (out), SYS_OVP_EN (out), CAN_L (bidir), CAN_H (bidir)
U_Rectifier = Rectifier.SchDoc: DC+ (out), DC- (out), LBS_out_1 (in), LBS_out_2 (in), LBS_out_3 (in), LBS_out_4 (in), LBS_out_5 (in), LBS_out_6 (in), LBS_out_7 (in), LBS_out_8 (in)

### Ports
Output+_1 (out), Output+_ 0 (out), Output-_0 (out), Output-_1 (out)

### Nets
+24V_CT: sheet Filter/+24V_CT, sheet Secondary Pad Auxiliary Wiring/CT_+24V
Curr_C1: sheet Filter/Curr_C1, sheet Secondary Pad Auxiliary Wiring/Curr_C1
Curr_C2: sheet Filter/Curr_C2, sheet Secondary Pad Auxiliary Wiring/Curr_C2
Curr_C3: sheet Filter/Curr_C3, sheet Secondary Pad Auxiliary Wiring/Curr_C3
Curr_C4: sheet Filter/Curr_C4, sheet Secondary Pad Auxiliary Wiring/Curr_C4
DC+: sheet Filter/DC+, sheet U_Rectifier/DC+
DC-: sheet Filter/DC-, sheet U_Rectifier/DC-
GND_CT: sheet Filter/GND_CT, sheet Secondary Pad Auxiliary Wiring/CT_GND
HVDC+: SCR.2(K) SCR.3 ; sheet Filter/HVDC+, sheet Filter/HVDC+ (monitoring), sheet Secondary Pad Auxiliary Wiring/HVDC+ (monitoring), sheet Secondary Pad Auxiliary Wiring/SCR_Cathode, sheet Secondary Pad Auxiliary Wiring/SCR_Gate
HVDC-: Ohmite_504SP1R0KG1#1.1 Ohmite_504SP1R0KG1#2.1 Ohmite_504SP1R0KG1#3.1 Ohmite_504SP1R0KG1#4.1 Ohmite_504SP1R0KG1#5.1 Ohmite_504SP1R0KG1#6.1 SPFJ-160.1 ; sheet Filter/HVDC-, sheet Filter/HVDC- (monitoring), sheet Secondary Pad Auxiliary Wiring/HVDC- (monitoring)
Isec1: Css1.1 Css2.1 L?#7.2 L?#8.2  [also labelled Isec2, n2]
LBS_out_1: Lbr1.2 ; sheet U_Rectifier/LBS_out_1
LBS_out_2: Lbr2.2 ; sheet U_Rectifier/LBS_out_2
LBS_out_3: Lbr3.2 ; sheet U_Rectifier/LBS_out_3
LBS_out_4: Lbr4.2 ; sheet U_Rectifier/LBS_out_4
LBS_out_5: Lbr5.2 ; sheet U_Rectifier/LBS_out_5
LBS_out_6: Lbr6.2 ; sheet U_Rectifier/LBS_out_6
LBS_out_7: Lbr7.2 ; sheet U_Rectifier/LBS_out_7
LBS_out_8: Lbr8.2 ; sheet U_Rectifier/LBS_out_8
n1: Css3.1 Css4.1 L?#9.2 L?#10.1
n3: Cps1.2 Cps2.2 Css1.2 Css2.2 Lbr1.1 Lbr2.1 Lbr3.1 Lbr4.1
n4: Cps1.1 Cps2.1 Css3.2 Css4.2 Lbr5.1 Lbr6.1 Lbr7.1 Lbr8.1
s2_chk: L?#8.1 L?#10.2
NetL?#7_1: L?#7.1 L?#9.1
NetOhmite_504SP1R0KG1#1_2: Ohmite_504SP1R0KG1#1.2 Ohmite_504SP1R0KG1#2.2 Ohmite_504SP1R0KG1#3.2 Ohmite_504SP1R0KG1#4.2 Ohmite_504SP1R0KG1#5.2 Ohmite_504SP1R0KG1#6.2 SCR.1(A) SPFJ-160.2
(unnamed): sheet Secondary Pad Auxiliary Wiring/CAN_L (BBB), sheet Secondary Pad Auxiliary Wiring/CAN_H (BBB), sheet Truck Cab Components/CAN_L, sheet Truck Cab Components/CAN_H
(unnamed): sheet Secondary Pad Auxiliary Wiring/Analog Current, sheet Truck Cab Components/Analog Current  [a separate net that carries the same name]
(unnamed): sheet Secondary Pad Auxiliary Wiring/24V_DC, sheet Truck Cab Components/24V_DC  [a separate net that carries the same name]
(unnamed): sheet Secondary Pad Auxiliary Wiring/DC_GND, sheet Truck Cab Components/DC_GND  [a separate net that carries the same name]

Not connected (* = marked no-connect by the designer): *?#1 9 10; *?#2 9 10; *?#3 9 10; *?#4 9 10

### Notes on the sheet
- WIRE_135
- Wires are part of the SCR
- WIRE_144
- WIRE_154
- WIRE_155
- Secondary Pad
- WIRE_217
- WIRE_219
- WIRE_209
- WIRE_212
- WIRE_215
- WIRE_218
- Secondary Coil
- (near Lbr1) Busbar Connections
- (near L?#8) Sec_set
- Bus Bar Connections
- (near L?#10) Sec_chk
- VS-ST330S16P1PBF
- Positive DC output busbar
- Secondary Pad Voltages/Currents (Peak, Mean, RMS)
- Negative DC output busbar
- (near *?#3) Inductive Absorber
- (near *?#4) Inductive Absorber
- Currents--
  through Isec1: 584A, 0A, 402A
  through Isec2: 539A, 0A, 371A
  through Isec_circ: 24A, 0A, 17A
  through capacitors Css1-4: 561A, 0A, 387A
  through capacitors Cps1-2: 1456A, 0A, 959A
  through inductors Lbr1-8: 627A, 0A, 419A
- at pre-filter output (Rec_DC+): 2506.98A, 1495.77A, 1676.55A
- Rectifer - Filter Currents (Peak, Mean, RMS)
- Voltages--
  across sec. XFMR side 1 (n2, s1_chk): 3035V, 360V, 1879V
  across sec. XFMR side 2 (n2, s2_chk): 3549V, 360V, 2230V
  at n1: 3320V, 360V, 2073V
  at n2: 3328V, 360V, 2073V
  at n3: 1508V, 360V, 879V
  at n4: 1506V, 360V, 879V
  at capacitors Css1-4: 2225V, 0V, 1523V
  at capacitors Cps1-2: 2296V, 0V, 1603V
  across inductors Lbr1-8: 1372V, 0V, 721V
  at output nodes LBS_out_1-8: 721V, 360V, 509V
- Labels drawn without touching a wire or pin: Isec_circ, Rec_DC+, Rec_DC-, s1_chk

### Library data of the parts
*?#1-*?#4 = CMP-006-000013-3: 59.6 uH Common Mode Inductor with coupling of 0.9996
Cps1 Cps2 = Capacitor: SimulationGenericComponent: True; Value: 1.128uF
Css1 = Capacitor: SimulationGenericComponent: True; Value: 500.02nF
Css2 = Capacitor: SimulationGenericComponent: True; Value: 499.16nF
Css3 = Capacitor: SimulationGenericComponent: True; Value: 499.07nF
Css4 = Capacitor: SimulationGenericComponent: True; Value: 499.73nF
L?#7-L?#10 = Inductor: SimulationGenericComponent: True; Value: 1u
Lbr1-Lbr8 = Inductor: SimulationGenericComponent: True; Value: 3.126uF
Ohmite_504SP1R0KG1#1-Ohmite_504SP1R0KG1#6 = Resistor: TC1: 0; SimulationGenericComponent: True
SCR = SCR: IH: 50MA; IGT: 40MA; TON: 1US; VTMIN: 1V; VDRM: 50V; DVDT: 50MEG; TQ: 20US; K1: 1; SimulationGenericComponent: True
SPFJ-160 = Fuse: RESISTANCE: 1m; SimulationGenericComponent: True

## Sheet Filter.SchDoc: <Document>
size Letter; Engineer: <Engineer>; Organization: UPEL; Address1: USU Power Electronics Lab; Address2: USTAR Building 620, RM 118; Address3: 1600 N 620 E; Address4: North Logan, UT 84341; DocumentNumber: 14; Revision: v1; SheetNumber: 14; SheetTotal: 16
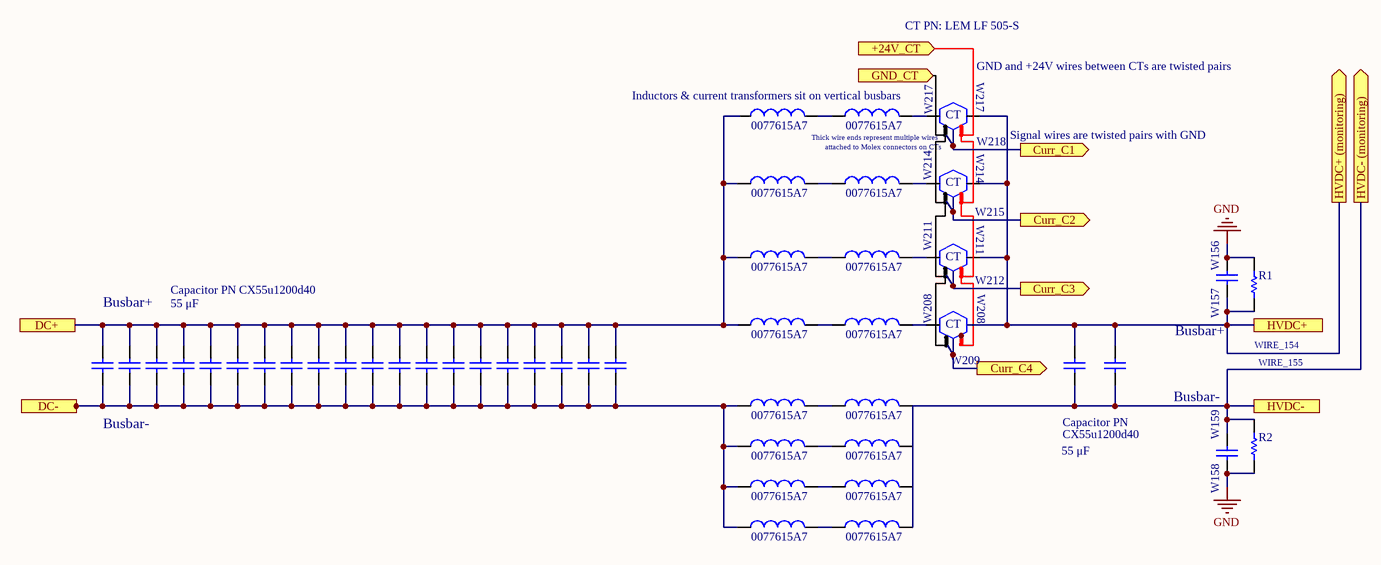
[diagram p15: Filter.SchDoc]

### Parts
(Parts that share a designator on the sheet are numbered #1, #2 ... from top to bottom, then left to right.)
*?#5  0077615A7
*?#6  0077615A7
*?#7  LEM LF 505-S  (value not drawn)
*?#8  0077615A7
*?#9  0077615A7
*?#10  LEM LF 505-S  (value not drawn)
*?#11  0077615A7
*?#12  0077615A7
*?#13  LEM LF 505-S  (value not drawn)
*?#14  0077615A7
*?#15  0077615A7
*?#16  CT PN: LEM LF 505-S
*?#17  0077615A7
*?#18  0077615A7
*?#19  0077615A7
*?#20  0077615A7
*?#21  0077615A7
*?#22  0077615A7
*?#23  0077615A7
*?#24  0077615A7
C?#1  Capacitor  (value not drawn)
C?#2  CX55u1200d40
C?#3  Capacitor PN CX55u1200d40
C?#4  Capacitor  (value not drawn)
C?#5  Capacitor  (value not drawn)
C?#6  Capacitor  (value not drawn)
C?#7  Capacitor  (value not drawn)
C?#8  Capacitor  (value not drawn)
C?#9  Capacitor  (value not drawn)
C?#10  Capacitor  (value not drawn)
C?#11  Capacitor  (value not drawn)
C?#12  Capacitor  (value not drawn)
C?#13  Capacitor  (value not drawn)
C?#14  Capacitor  (value not drawn)
C?#15  Capacitor  (value not drawn)
C?#16  Capacitor  (value not drawn)
C?#17  Capacitor  (value not drawn)
C?#18  Capacitor  (value not drawn)
C?#19  Capacitor  (value not drawn)
C?#20  Capacitor  (value not drawn)
C?#21  Capacitor  (value not drawn)
C?#22  Capacitor  (value not drawn)
C?#23  944U470K122AA  (value not drawn)
C?#24  Capacitor  (value not drawn)
R1  10k  [0603 RESISTOR]  (value not drawn)
R2  10k  [0603 RESISTOR]  (value not drawn)

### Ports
+24V_CT (in), Curr_C1 (out), Curr_C2 (out), Curr_C3 (out), Curr_C4 (out), DC+, DC-, GND_CT (in), HVDC+, HVDC+ (monitoring) (out), HVDC-, HVDC- (monitoring) (out)

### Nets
GND: C?#1.1 C?#24.1 R1.2 R2.2
DC+: C?#3.2 C?#4.2 C?#5.2 C?#6.2 C?#7.2 C?#8.2 C?#9.2 C?#10.2 C?#11.2 C?#12.2 C?#13.2 C?#14.2 C?#15.2 C?#16.2 C?#17.2 C?#18.2 C?#19.2 C?#20.2 C?#21.2 C?#22.2 ; port DC+
DC-: C?#3.1 C?#4.1 C?#5.1 C?#6.1 C?#7.1 C?#8.1 C?#9.1 C?#10.1 C?#11.1 C?#12.1 C?#13.1 C?#14.1 C?#15.1 C?#16.1 C?#17.1 C?#18.1 C?#19.1 C?#20.1 C?#21.1 C?#22.1 ; port DC-
HVDC+: *?#16.8 C?#1.2 C?#2.1 C?#23.2 R1.1 ; port HVDC+, port HVDC+ (monitoring)
HVDC-: C?#2.2 C?#23.1 C?#24.2 R2.1 ; port HVDC-, port HVDC- (monitoring)

Not connected (* = marked no-connect by the designer): *?#5 11 12; *?#6 11 12; *?#7 7 8; *?#8 11 12; *?#9 11 12; *?#10 7 8; *?#11 11 12; *?#12 11 12; *?#13 7 8; *?#14 11 12; *?#15 11 12; *?#16 7; *?#17 11 12; *?#18 11 12; *?#19 11 12; *?#20 11 12; *?#21 11 12; *?#22 11 12; *?#23 11 12; *?#24 11 12

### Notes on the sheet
- (near *?#7) W217
- (near *?#7) GND and +24V wires between CTs are twisted pairs
- (near *?#7) Inductors & current transformers sit on vertical busbars
- (near *?#7) Thick wire ends represent multiple wires
- (near *?#7) attached to Molex connectors on CTs
- (near *?#10) W214
- (near *?#7) W218
- (near *?#7) Signal wires are twisted pairs with GND
- (near *?#10) W215
- (near *?#13) W211
- (near *?#13) W212
- (near C?#1) W156
- (near C?#4) Busbar+
- (near C?#6) 55 μF
- (near *?#16) W208
- Busbar+
- (near C?#1) W157
- WIRE_154
- (near *?#16) W209
- Busbar-
- WIRE_155
- (near C?#4) Busbar-
- 55 μF
- (near C?#23) Capacitor PN
- (near C?#24) W159
- (near C?#24) W158

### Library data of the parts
*?#5 *?#6 *?#8 *?#9 *?#11 *?#12 *?#14 *?#15 *?#17-*?#24 = CMP-006-000014-3: 116.8 nH Toroid
*?#7 *?#10 *?#13 *?#16 = Current_Sensor
C?#1-C?#24 = Capacitor: SimulationGenericComponent: True; Value: 1p
R1 R2 = CRCW060310K0FKEA: 10 kOhms ±1% 0.1W, 1/10W Chip Resistor 0603 (1608 Metric) Automotive AEC-Q200 Thick Film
